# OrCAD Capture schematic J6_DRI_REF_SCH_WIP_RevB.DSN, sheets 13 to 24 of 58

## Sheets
13 SH15 - VAYU CLOCKS: size B; rev: A
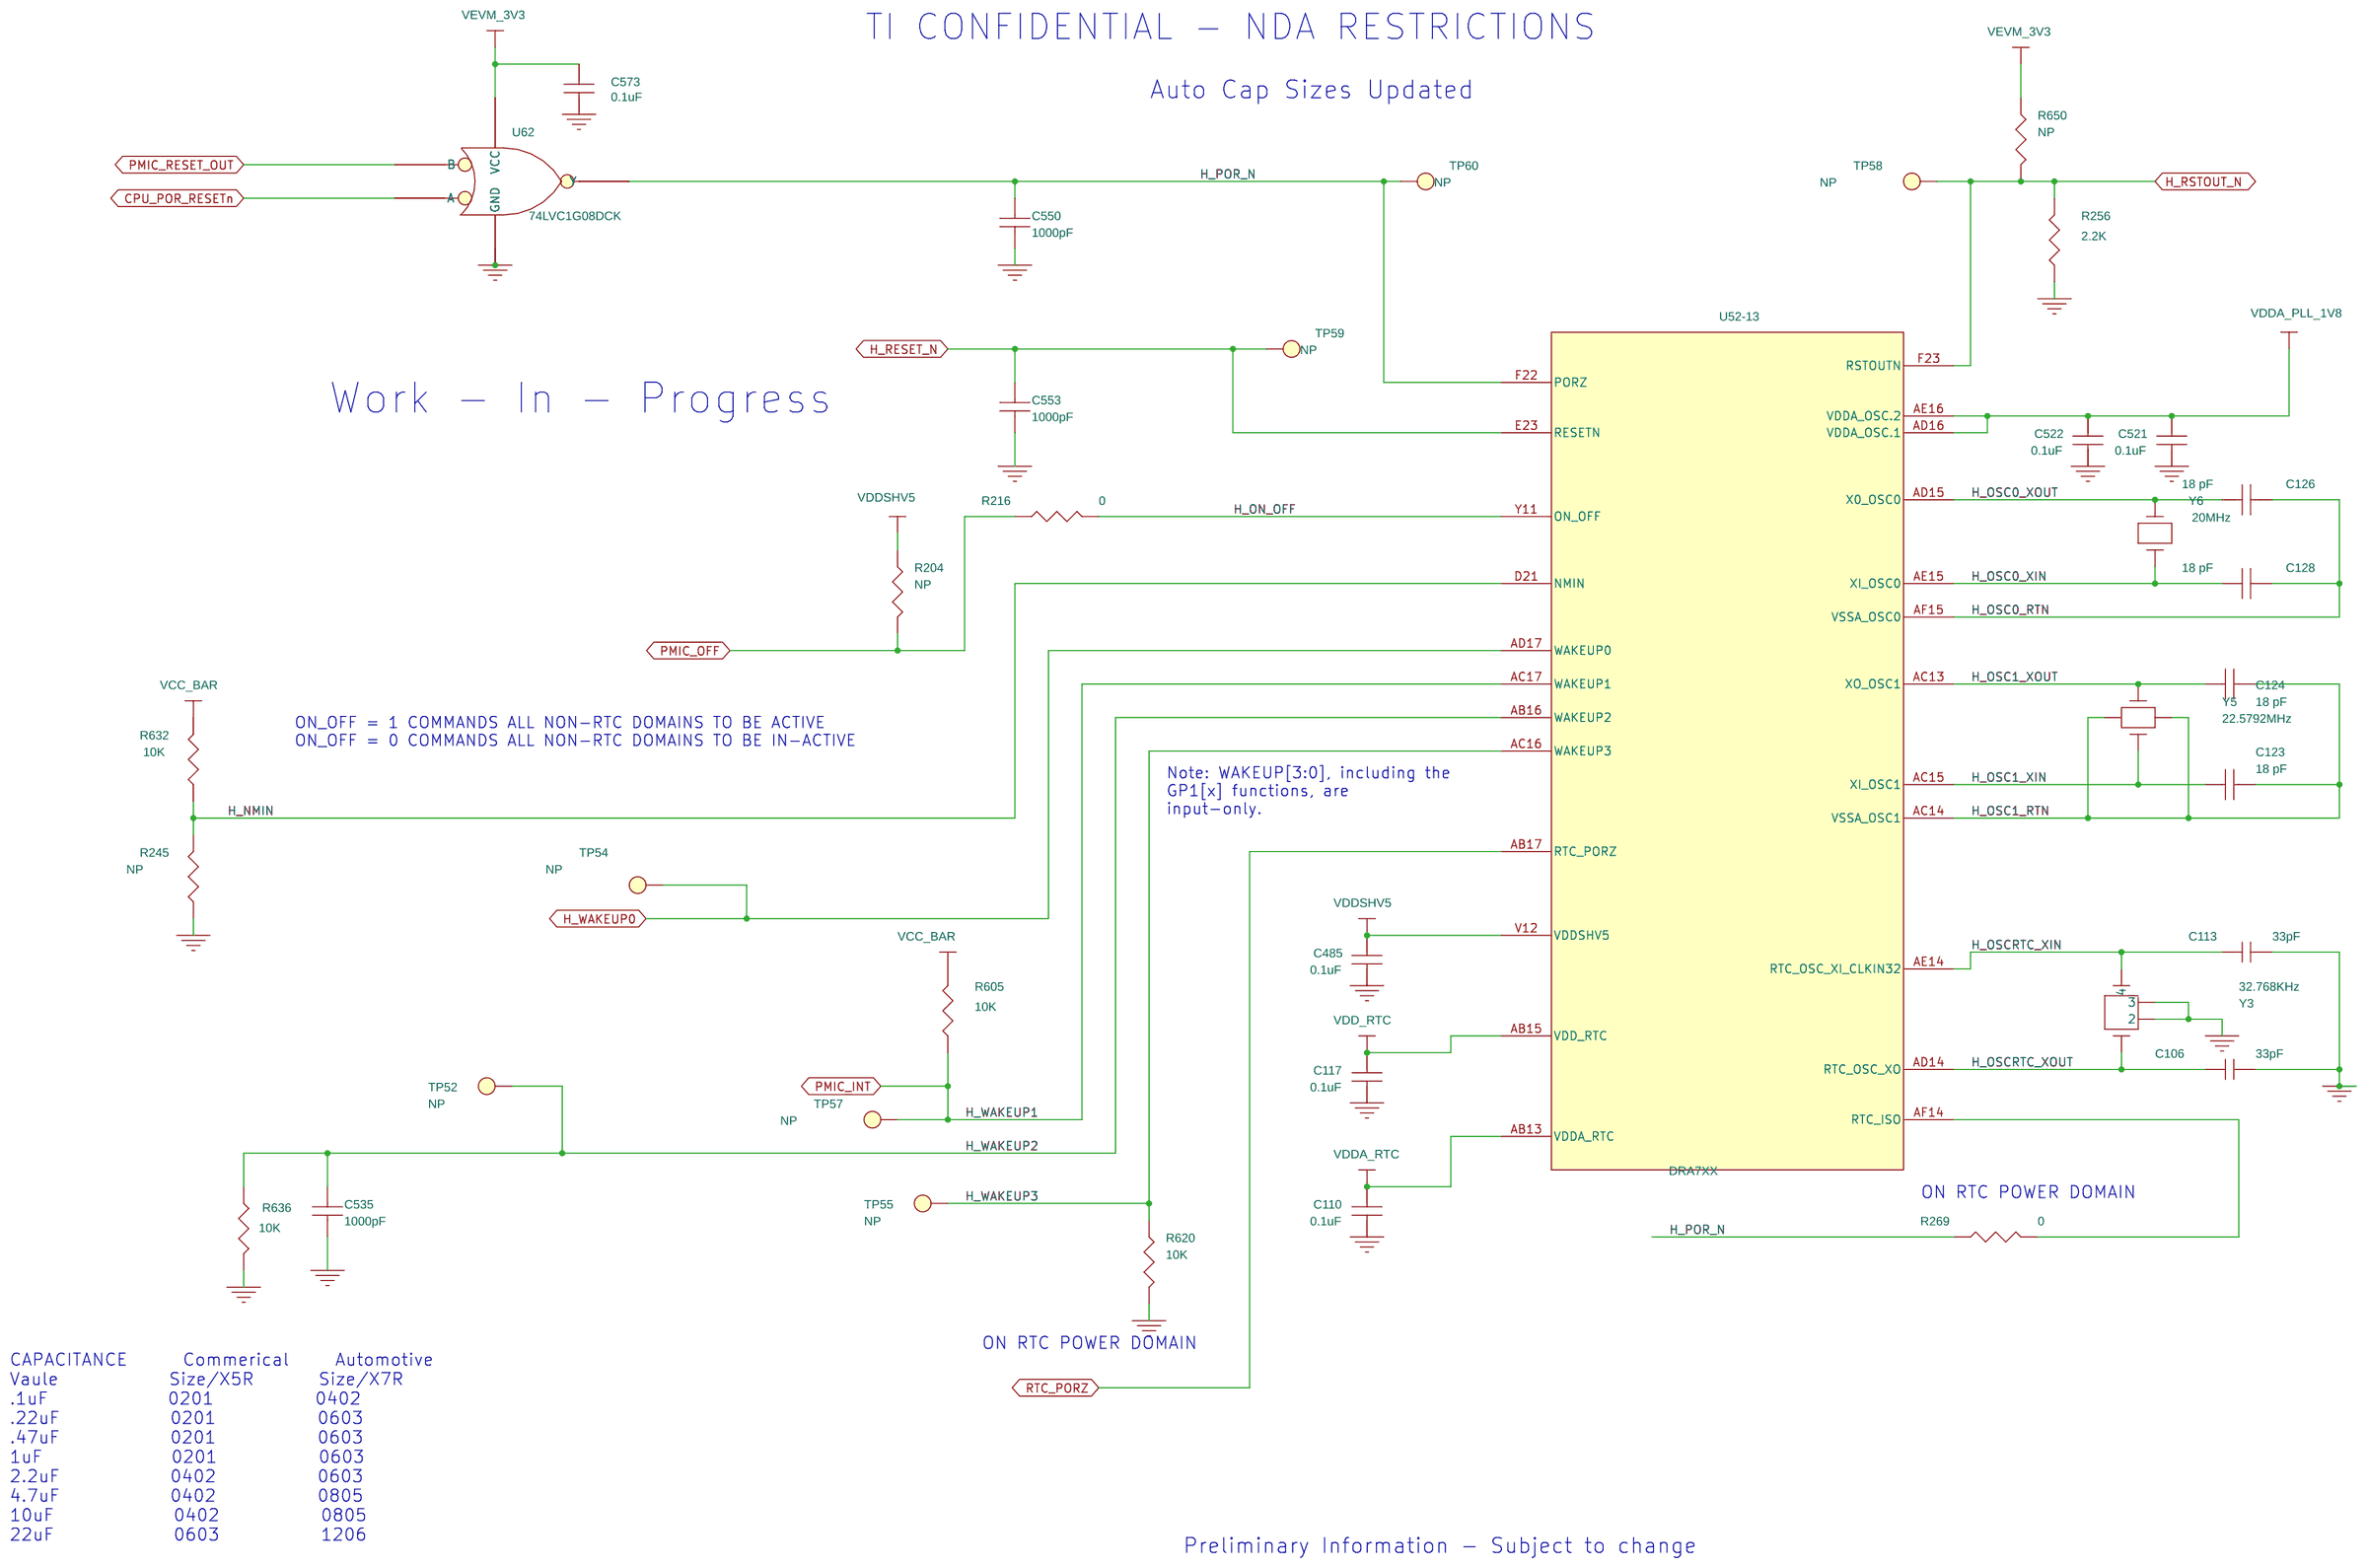
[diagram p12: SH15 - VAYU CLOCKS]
14 SH16 - VAYU INTERNAL LDOS: size B; rev: A
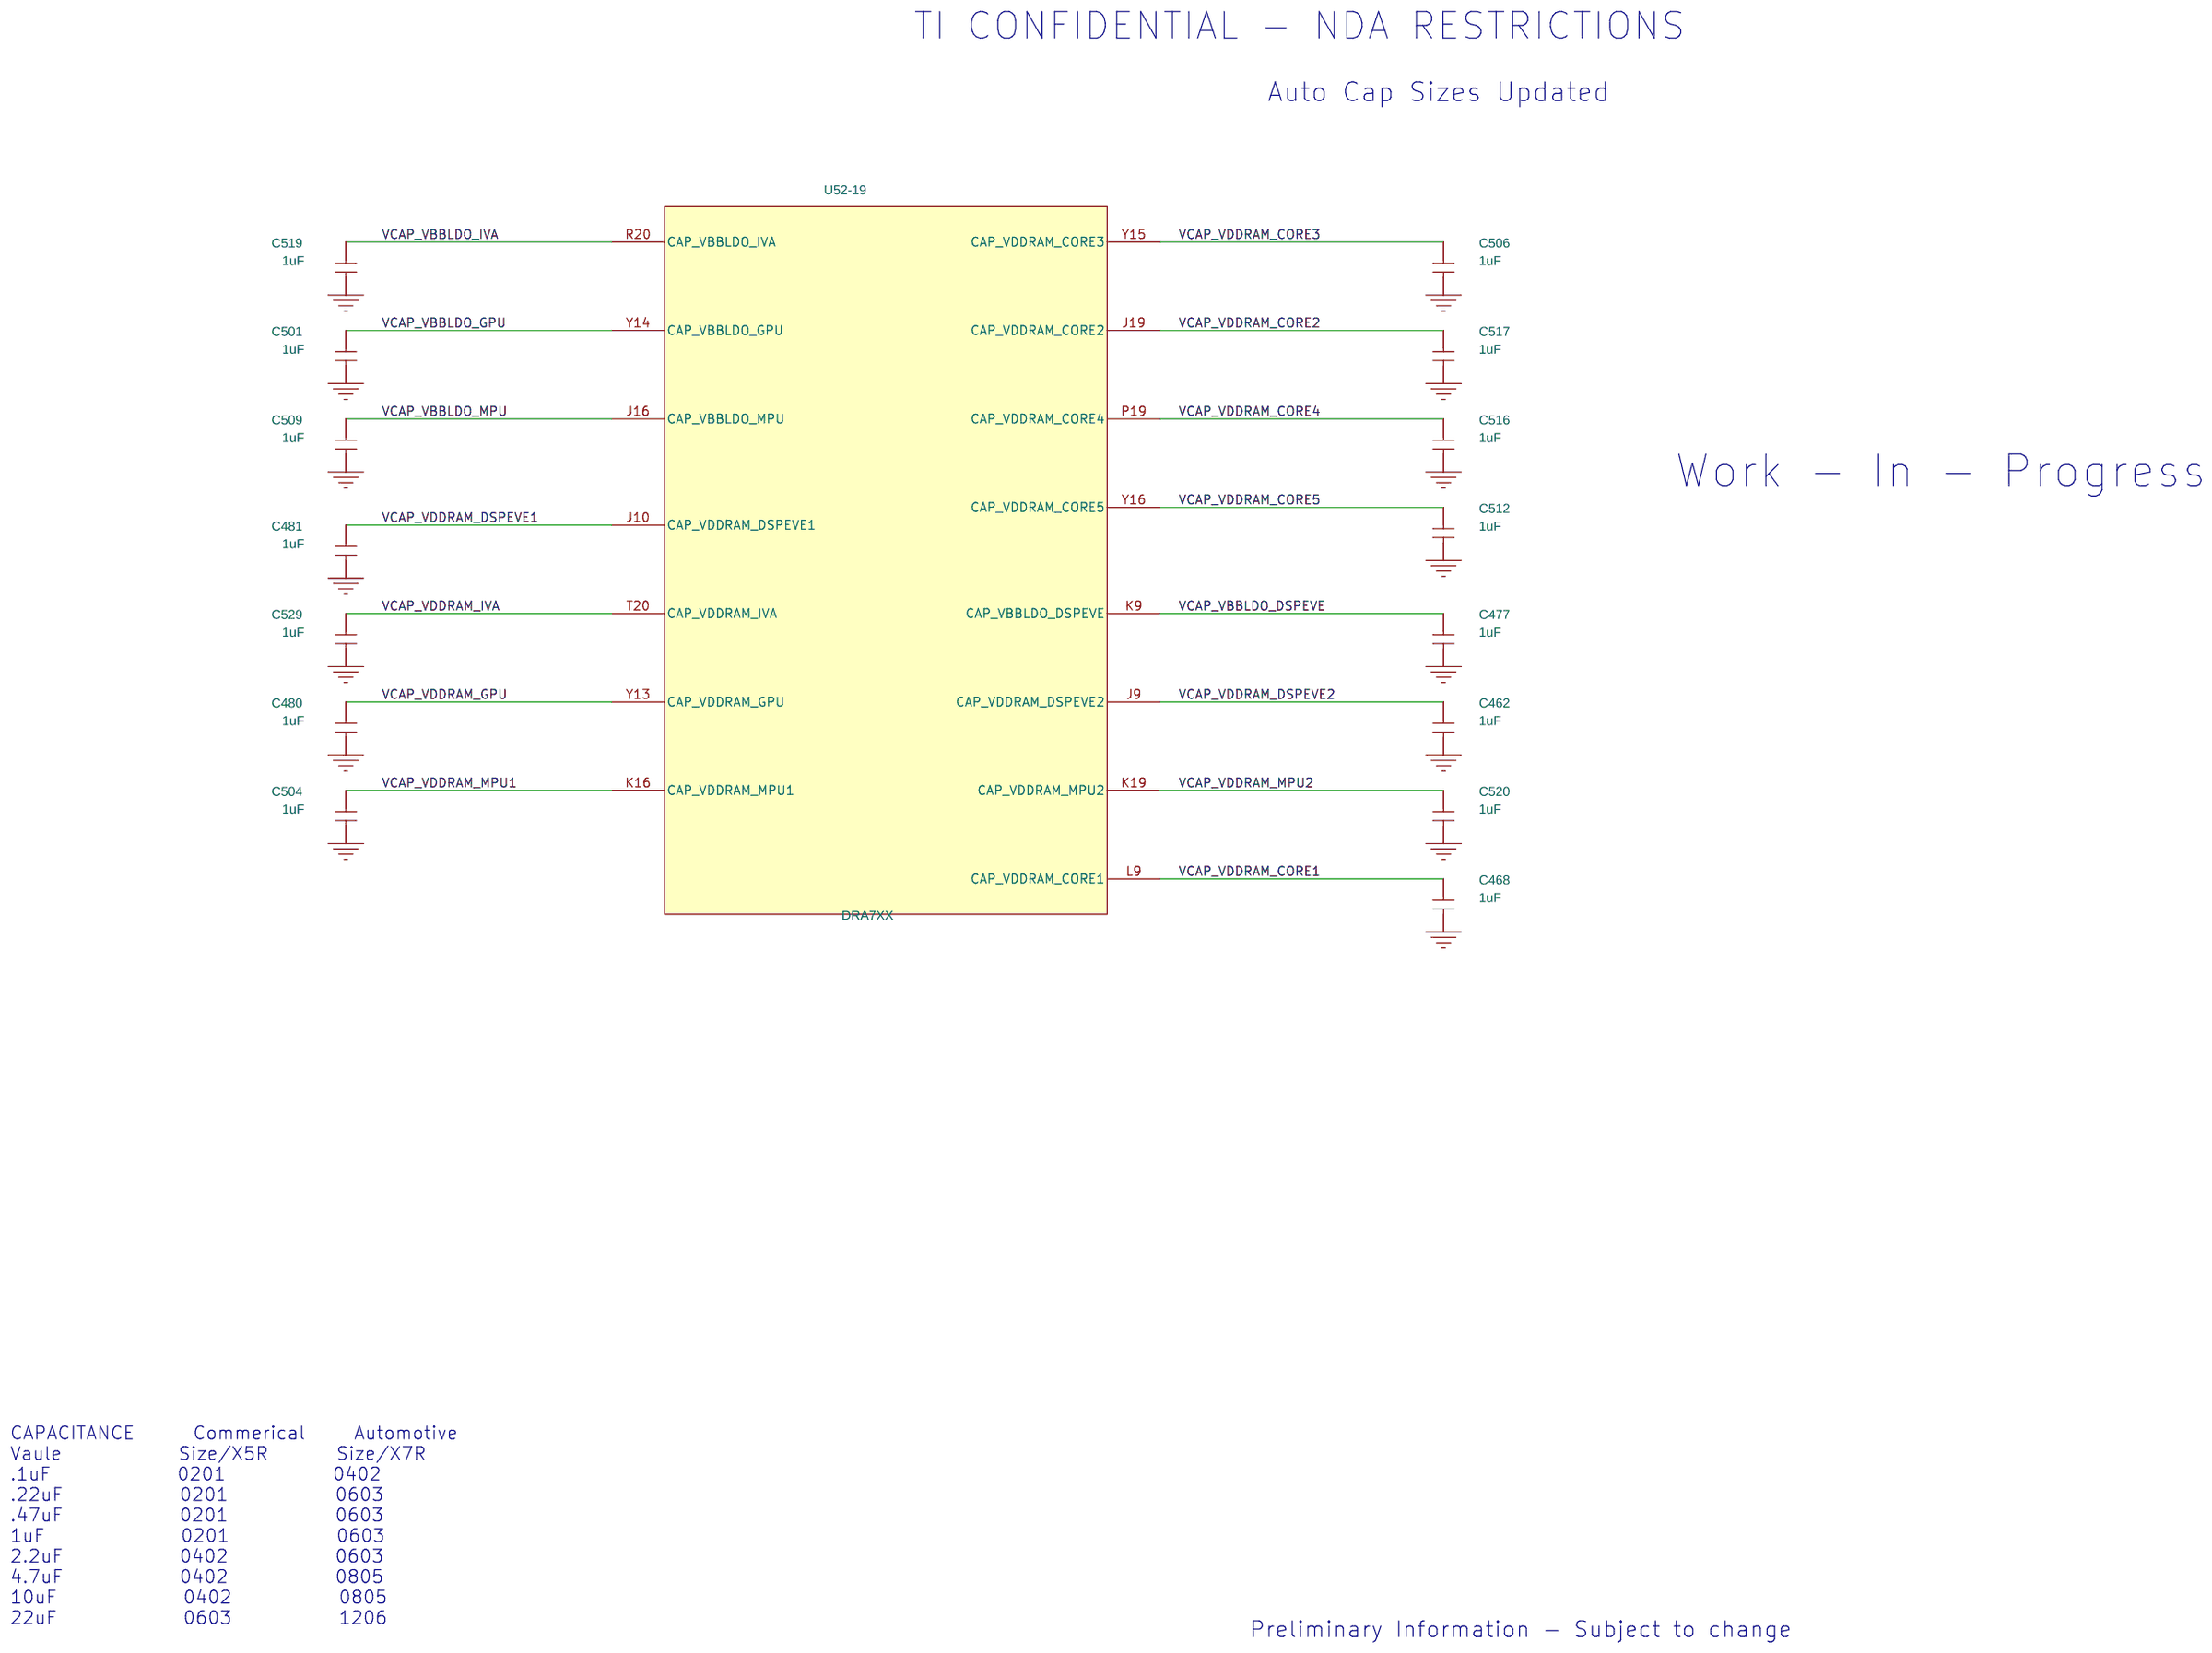
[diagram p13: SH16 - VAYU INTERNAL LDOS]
15 SH17 - VAYU IO POWER: size B; rev: A
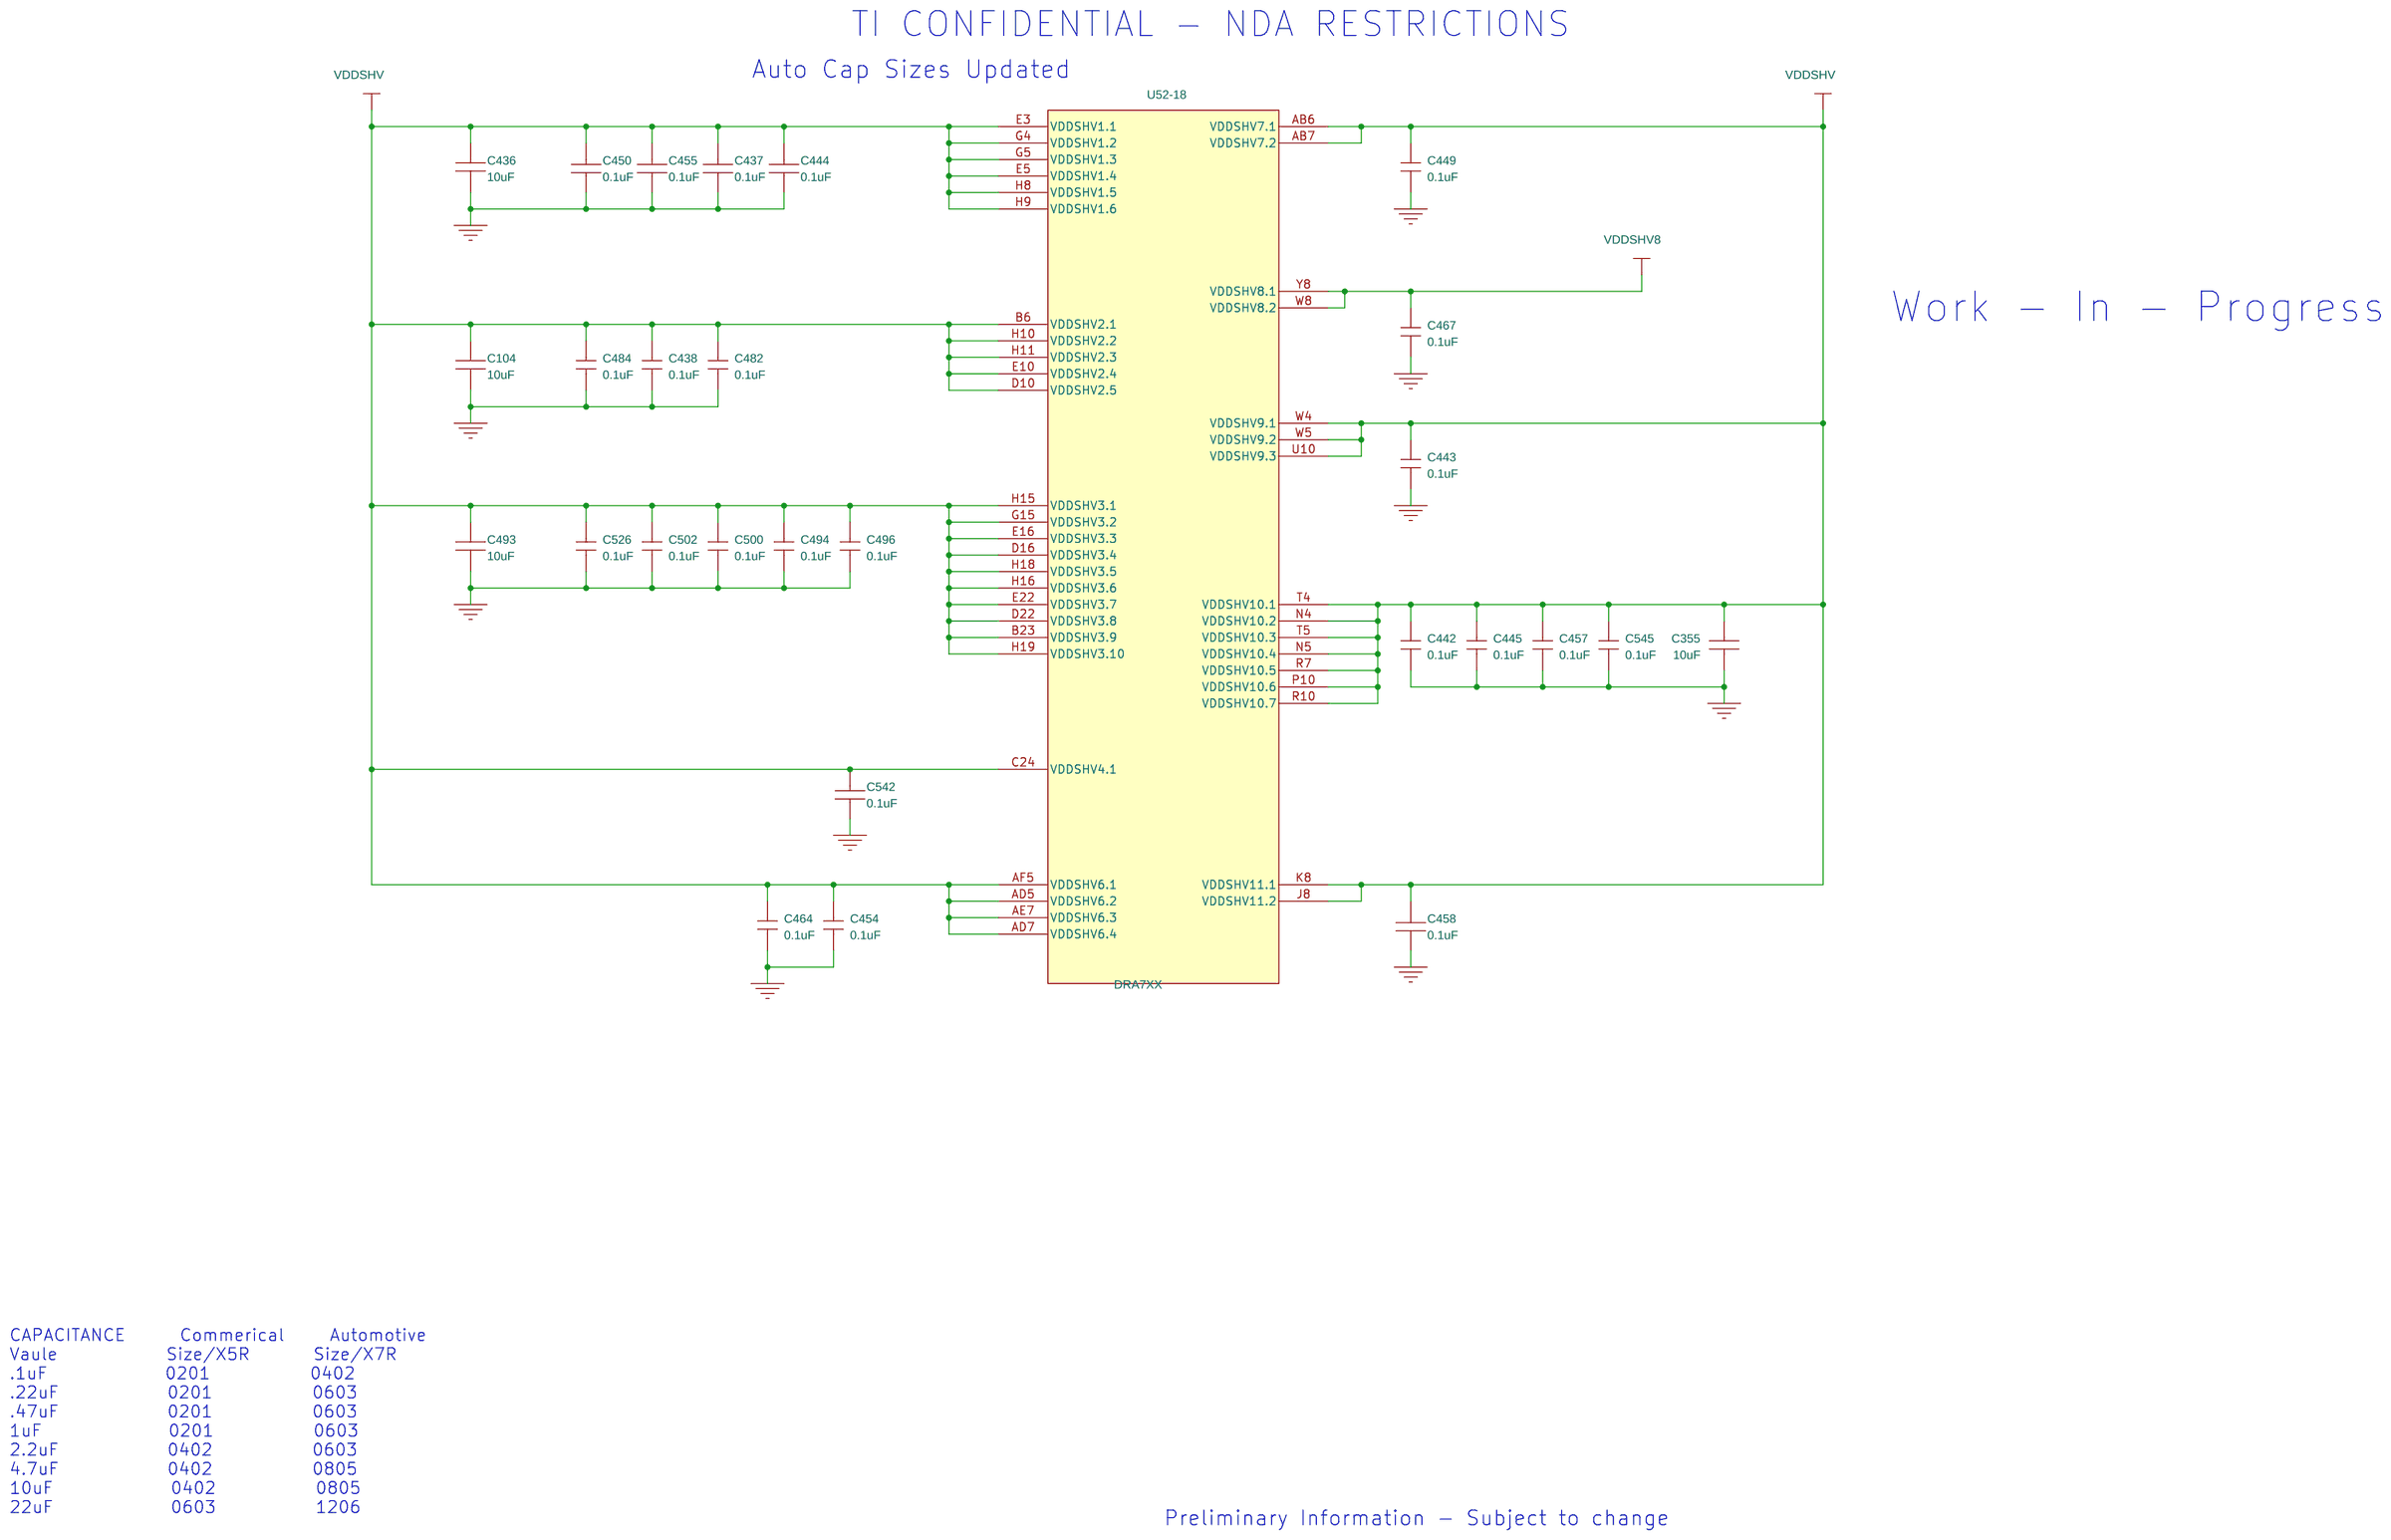
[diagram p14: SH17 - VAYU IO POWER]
16 SH18 - VAYU 1V8 DIGITAL POWER: size B; rev: A
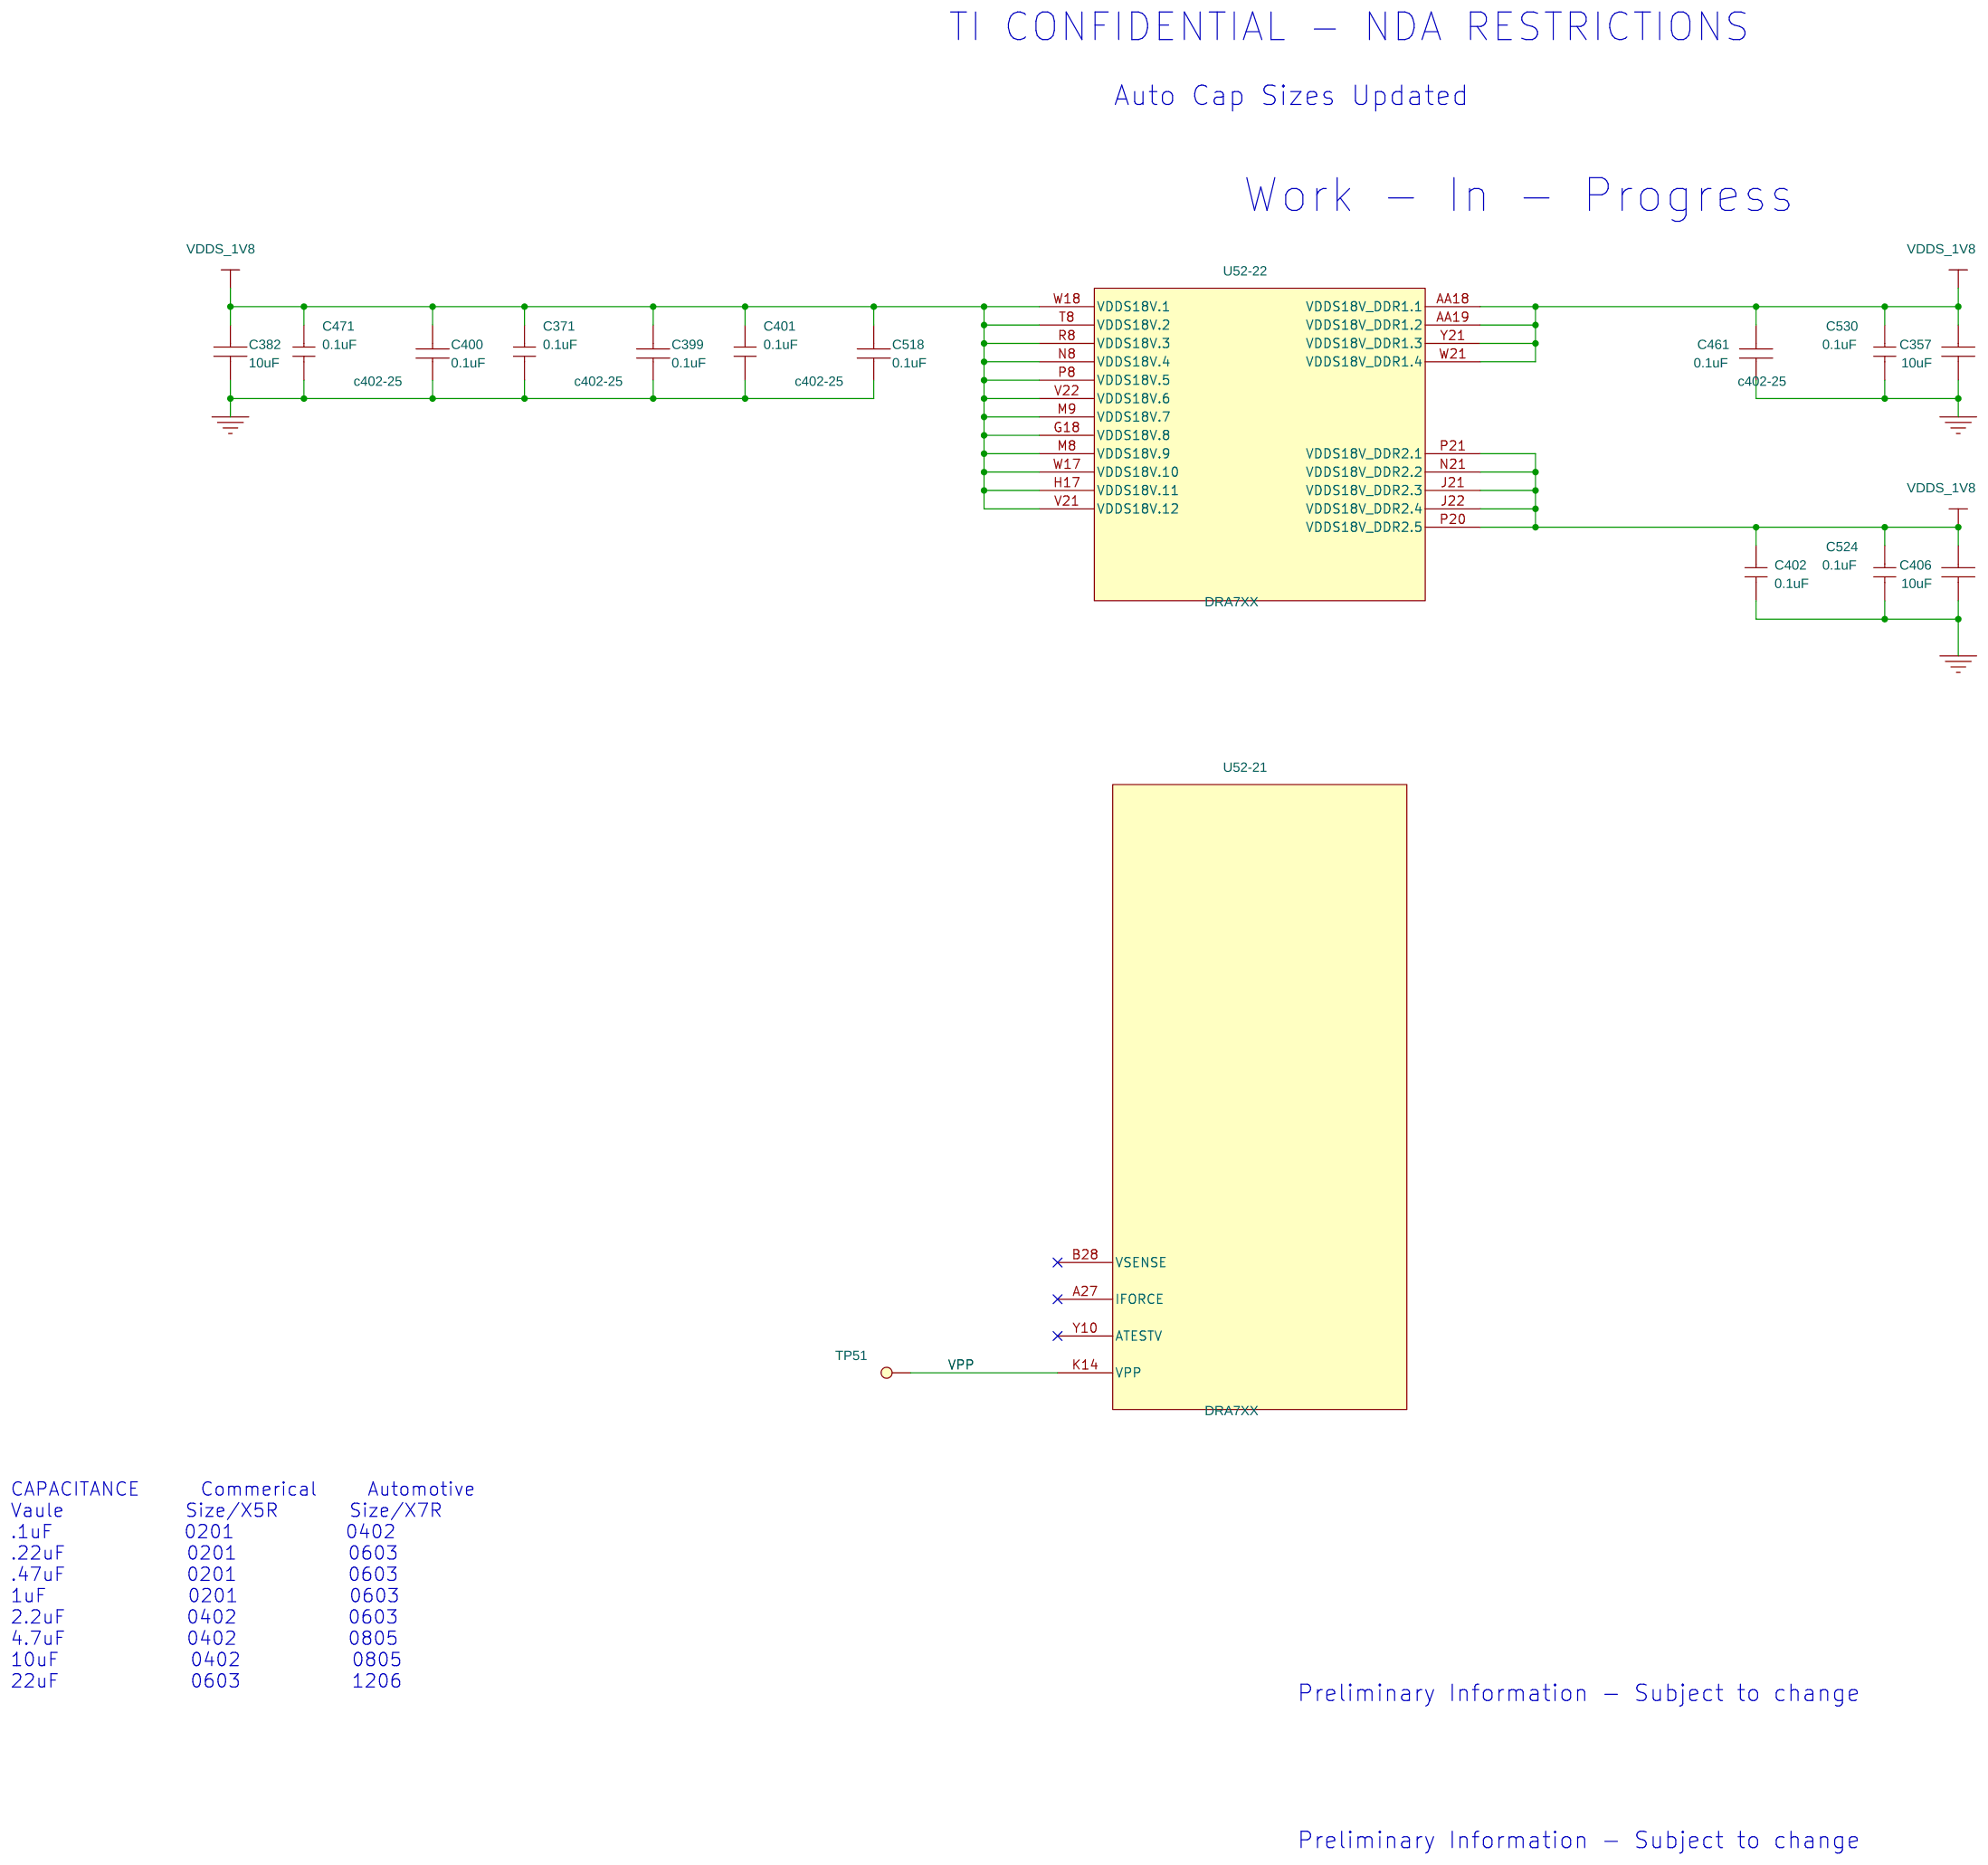
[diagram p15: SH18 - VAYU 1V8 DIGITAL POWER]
17 SH19 - VAYU DDR POWER: size B
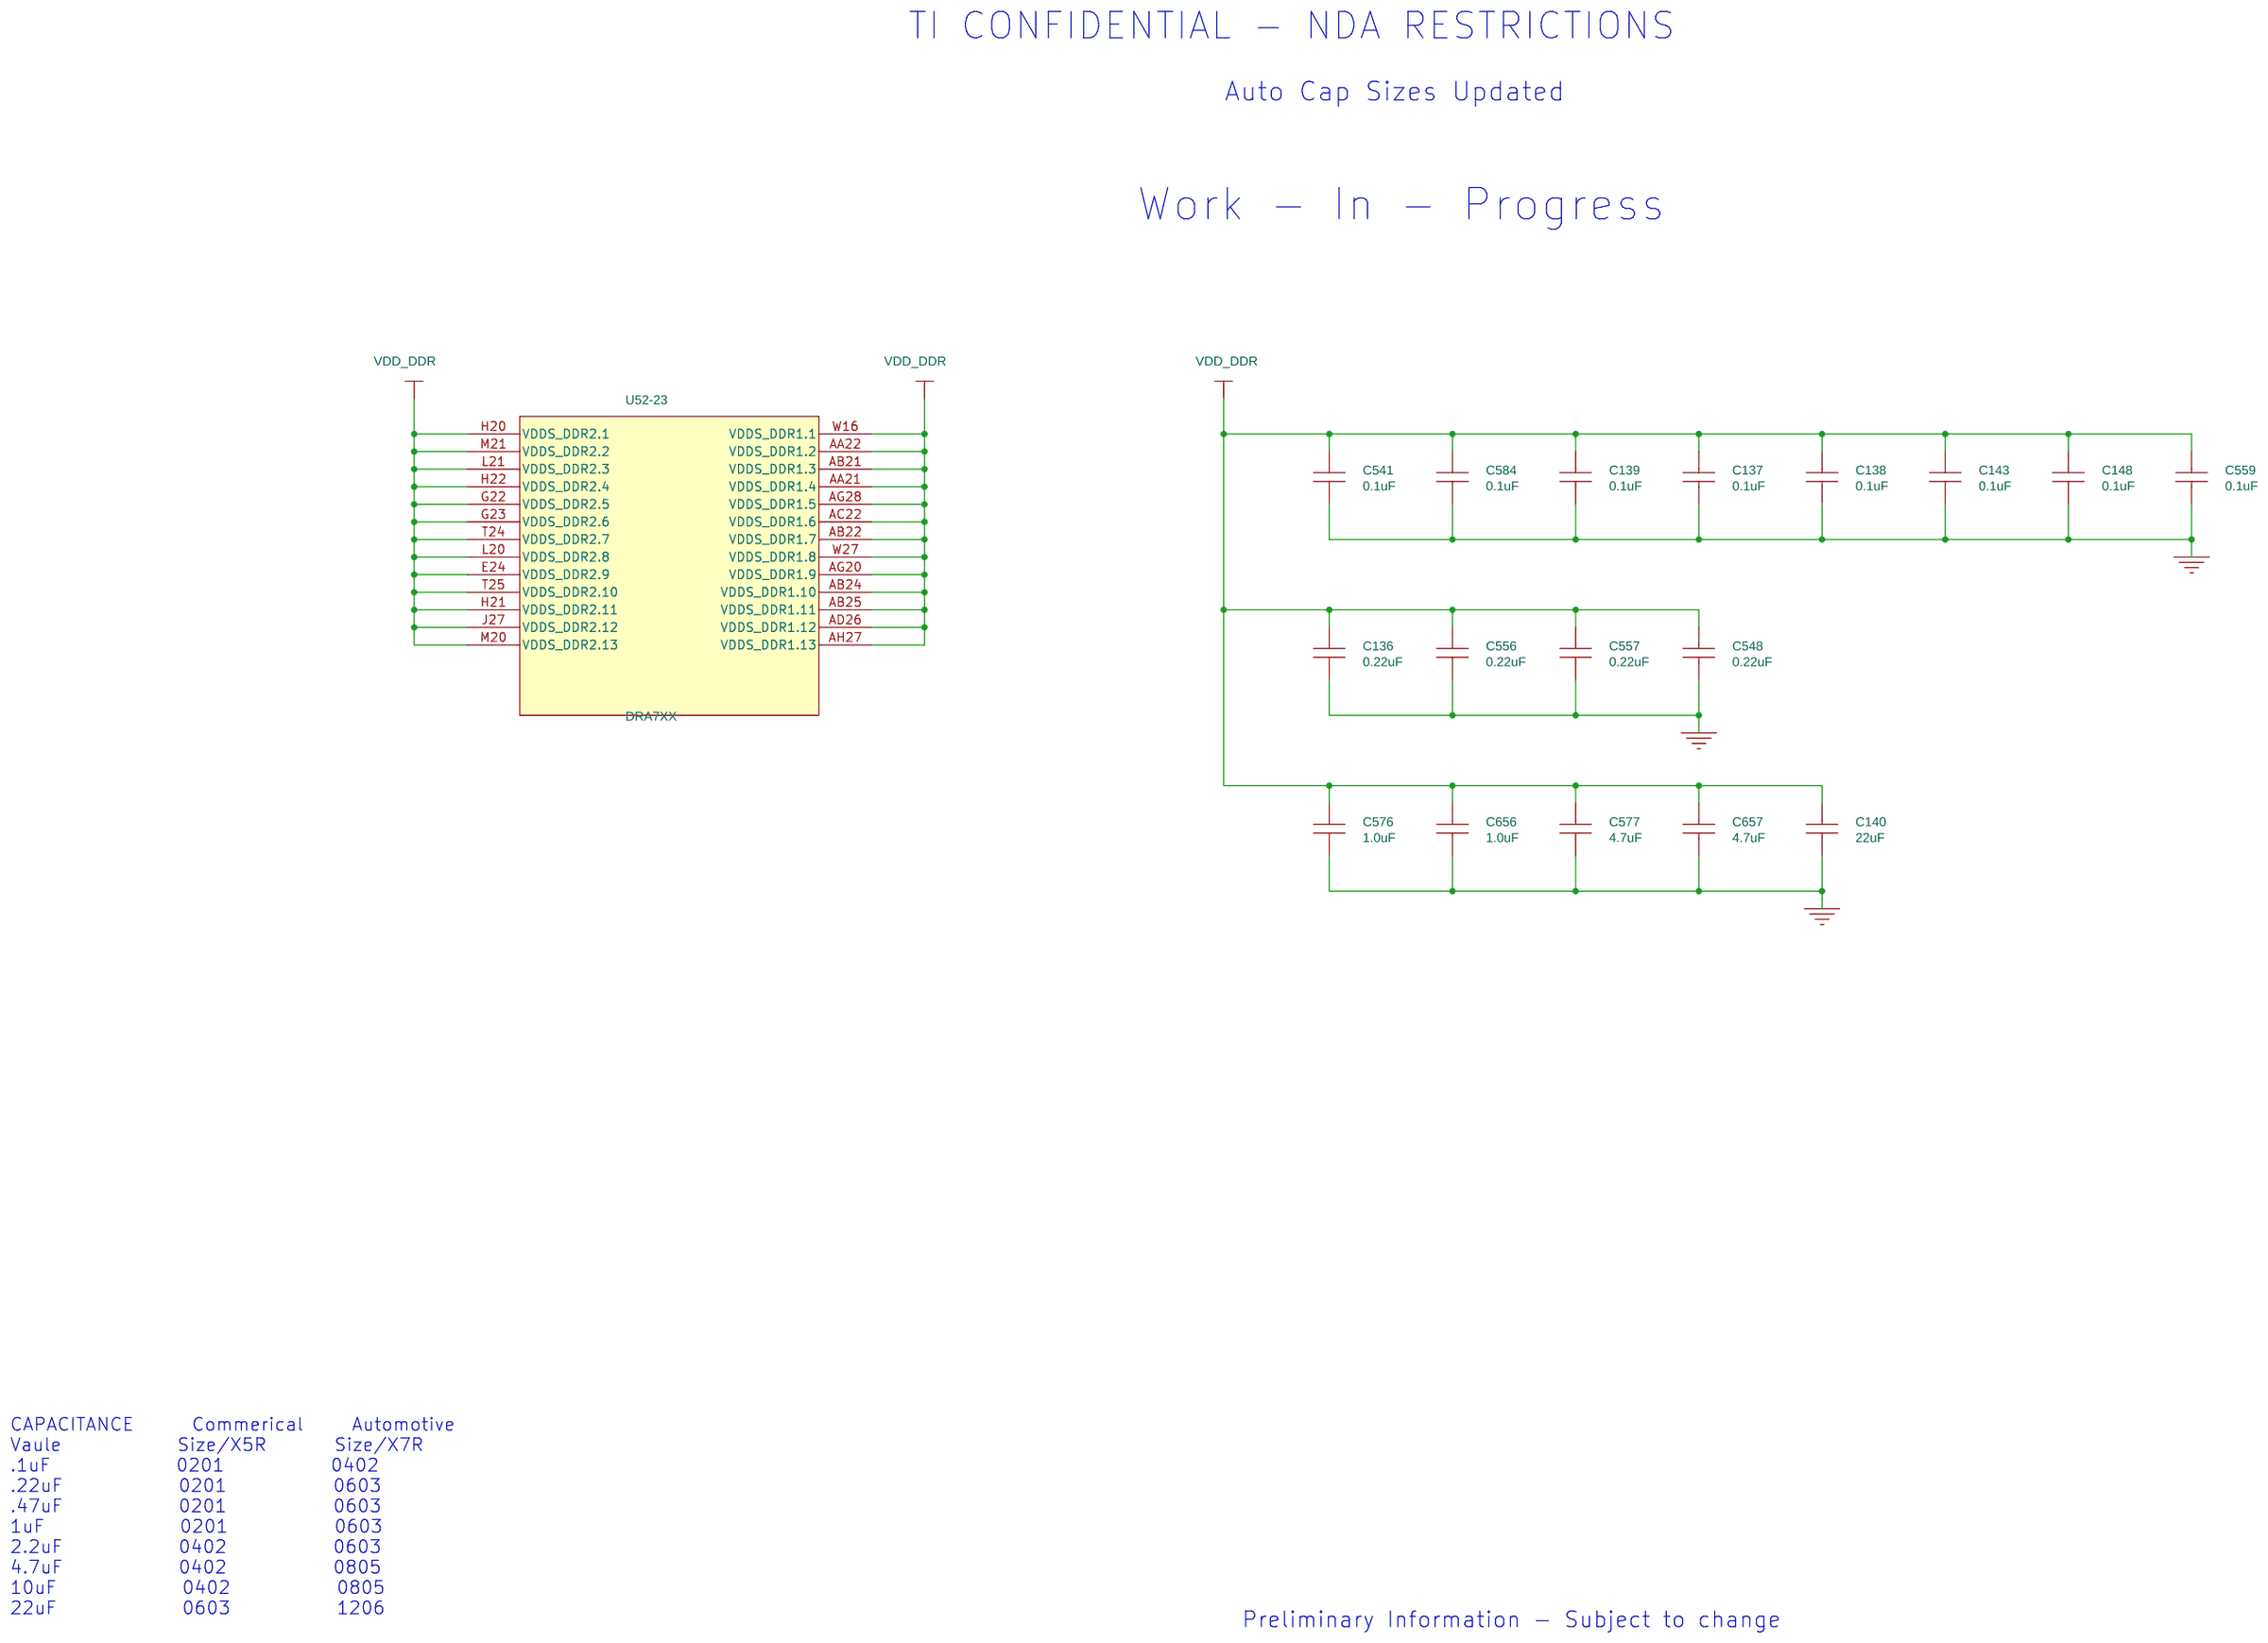
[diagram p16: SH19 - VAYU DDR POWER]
18 SH20 - VAYU 1V8 ANALOG POWER: size B; rev: A
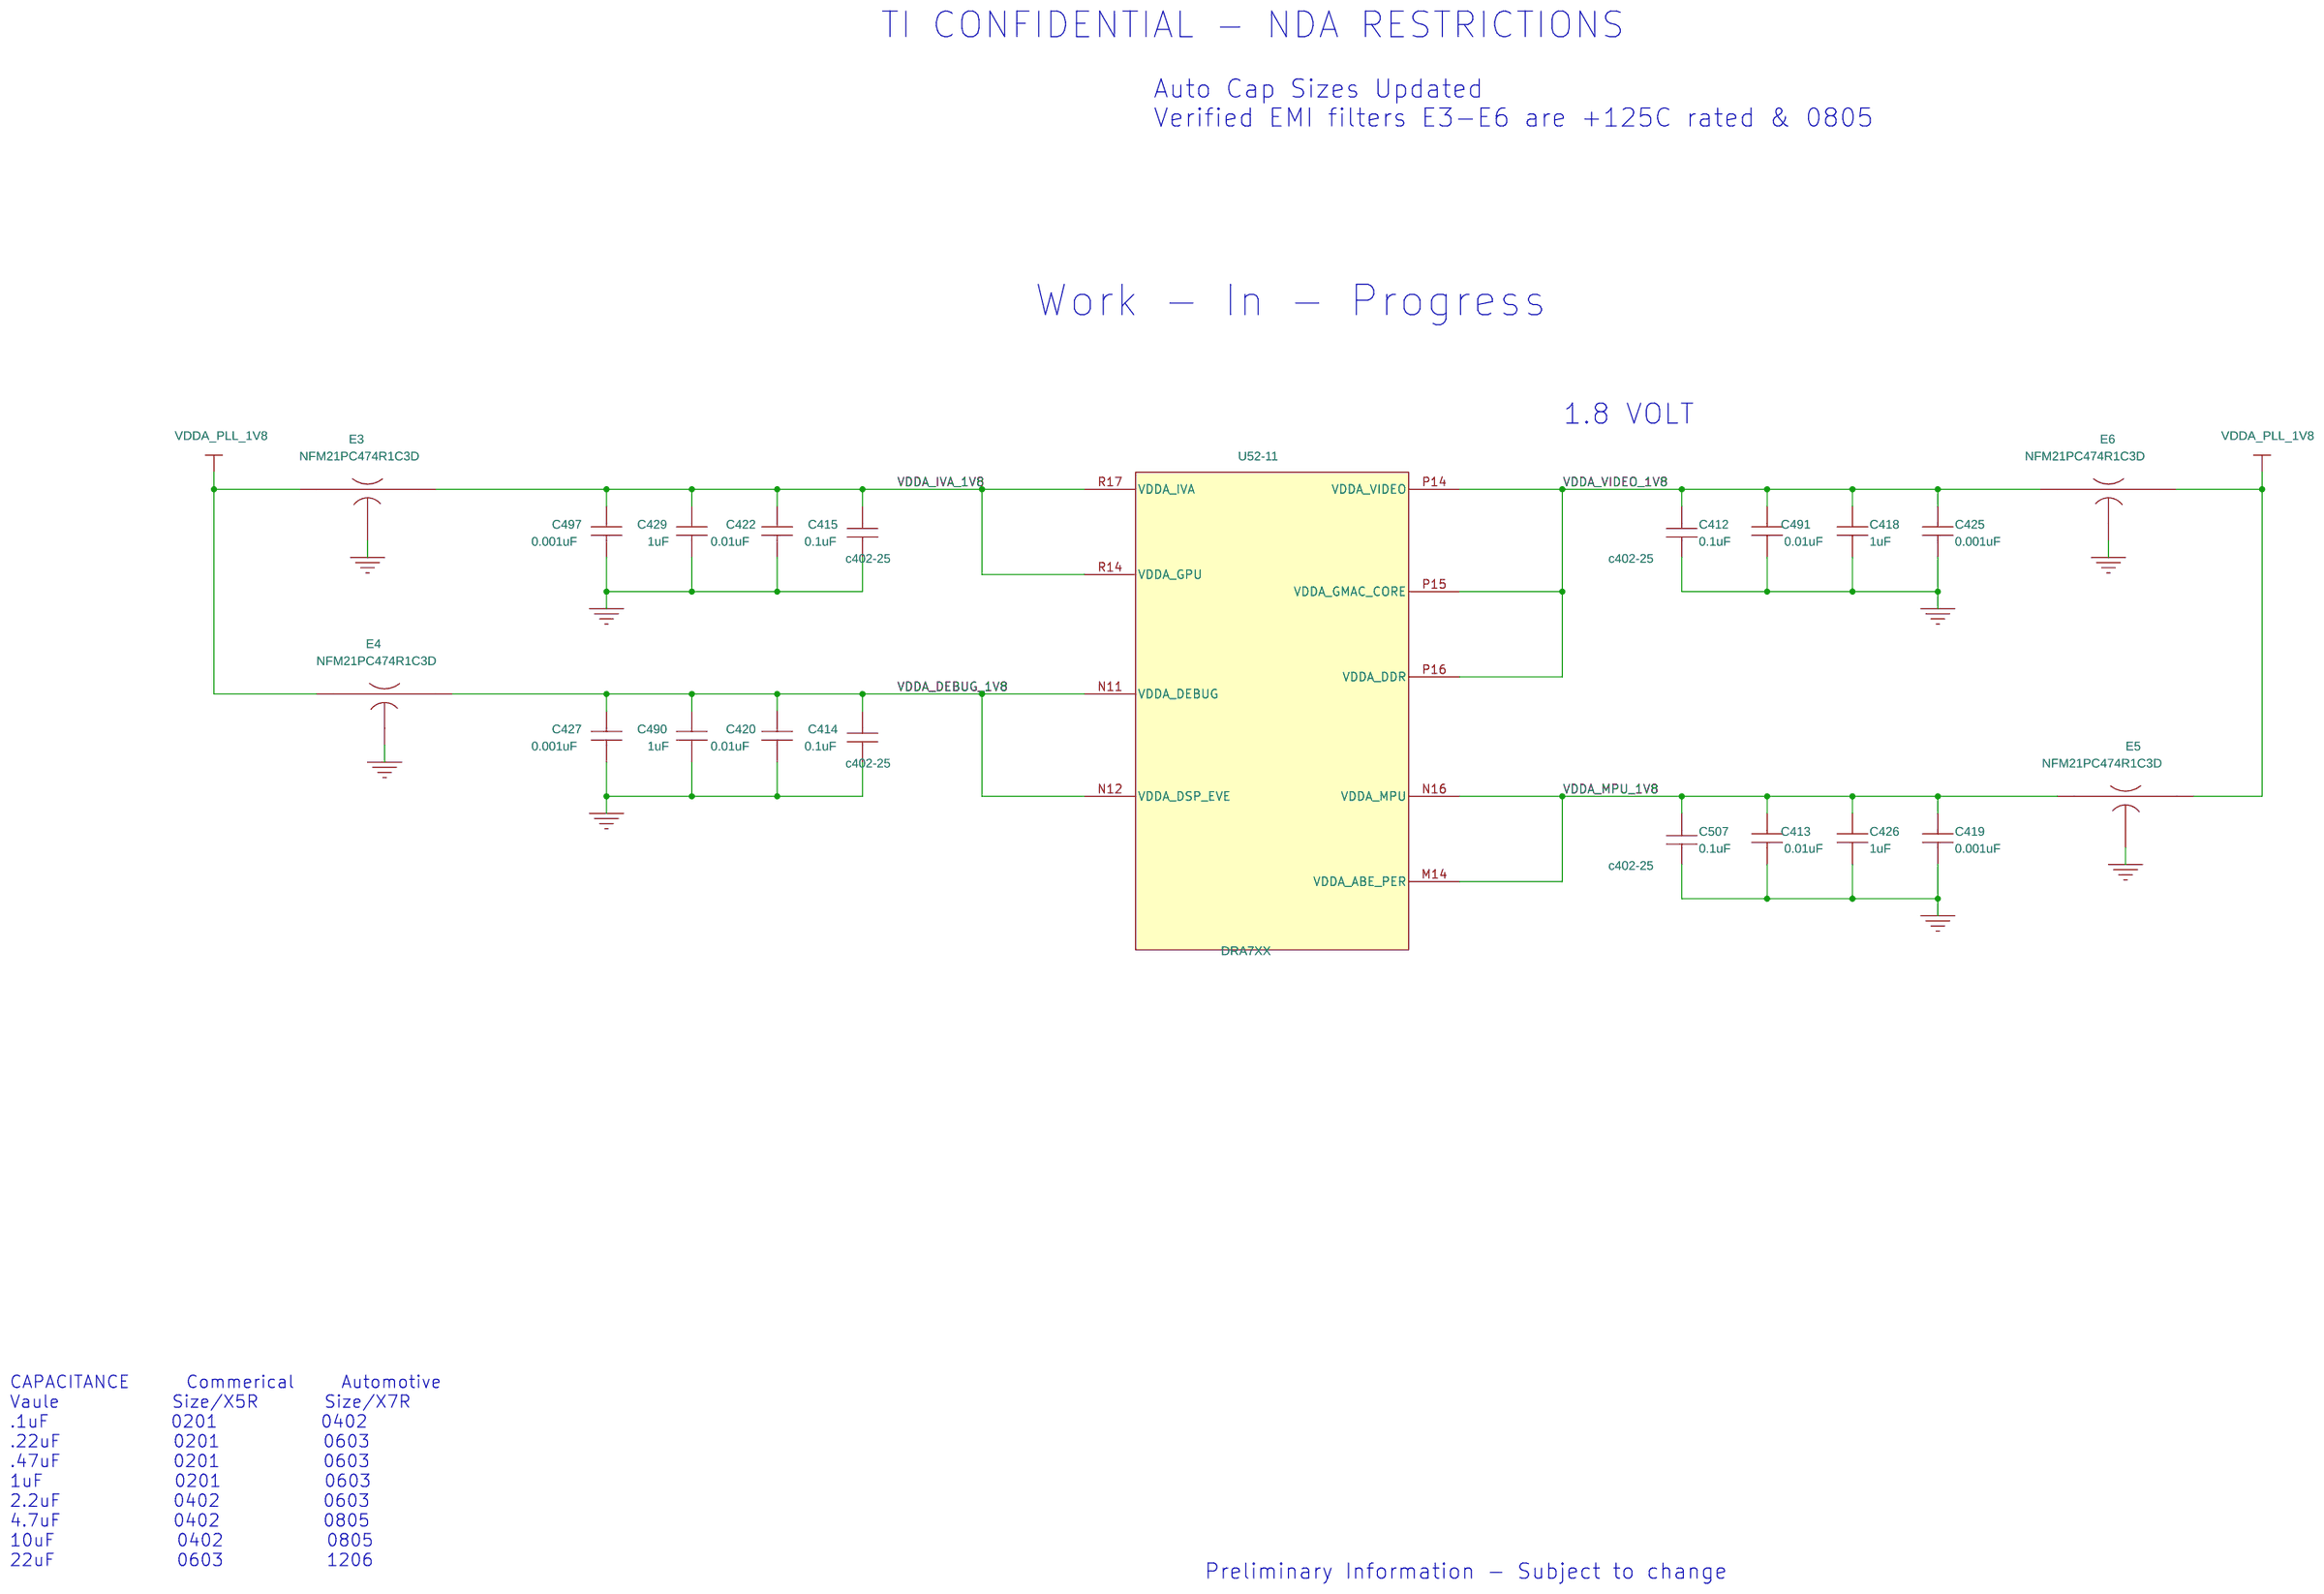
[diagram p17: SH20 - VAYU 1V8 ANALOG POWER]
19 SH21 - VAYU AVS POWER: size B
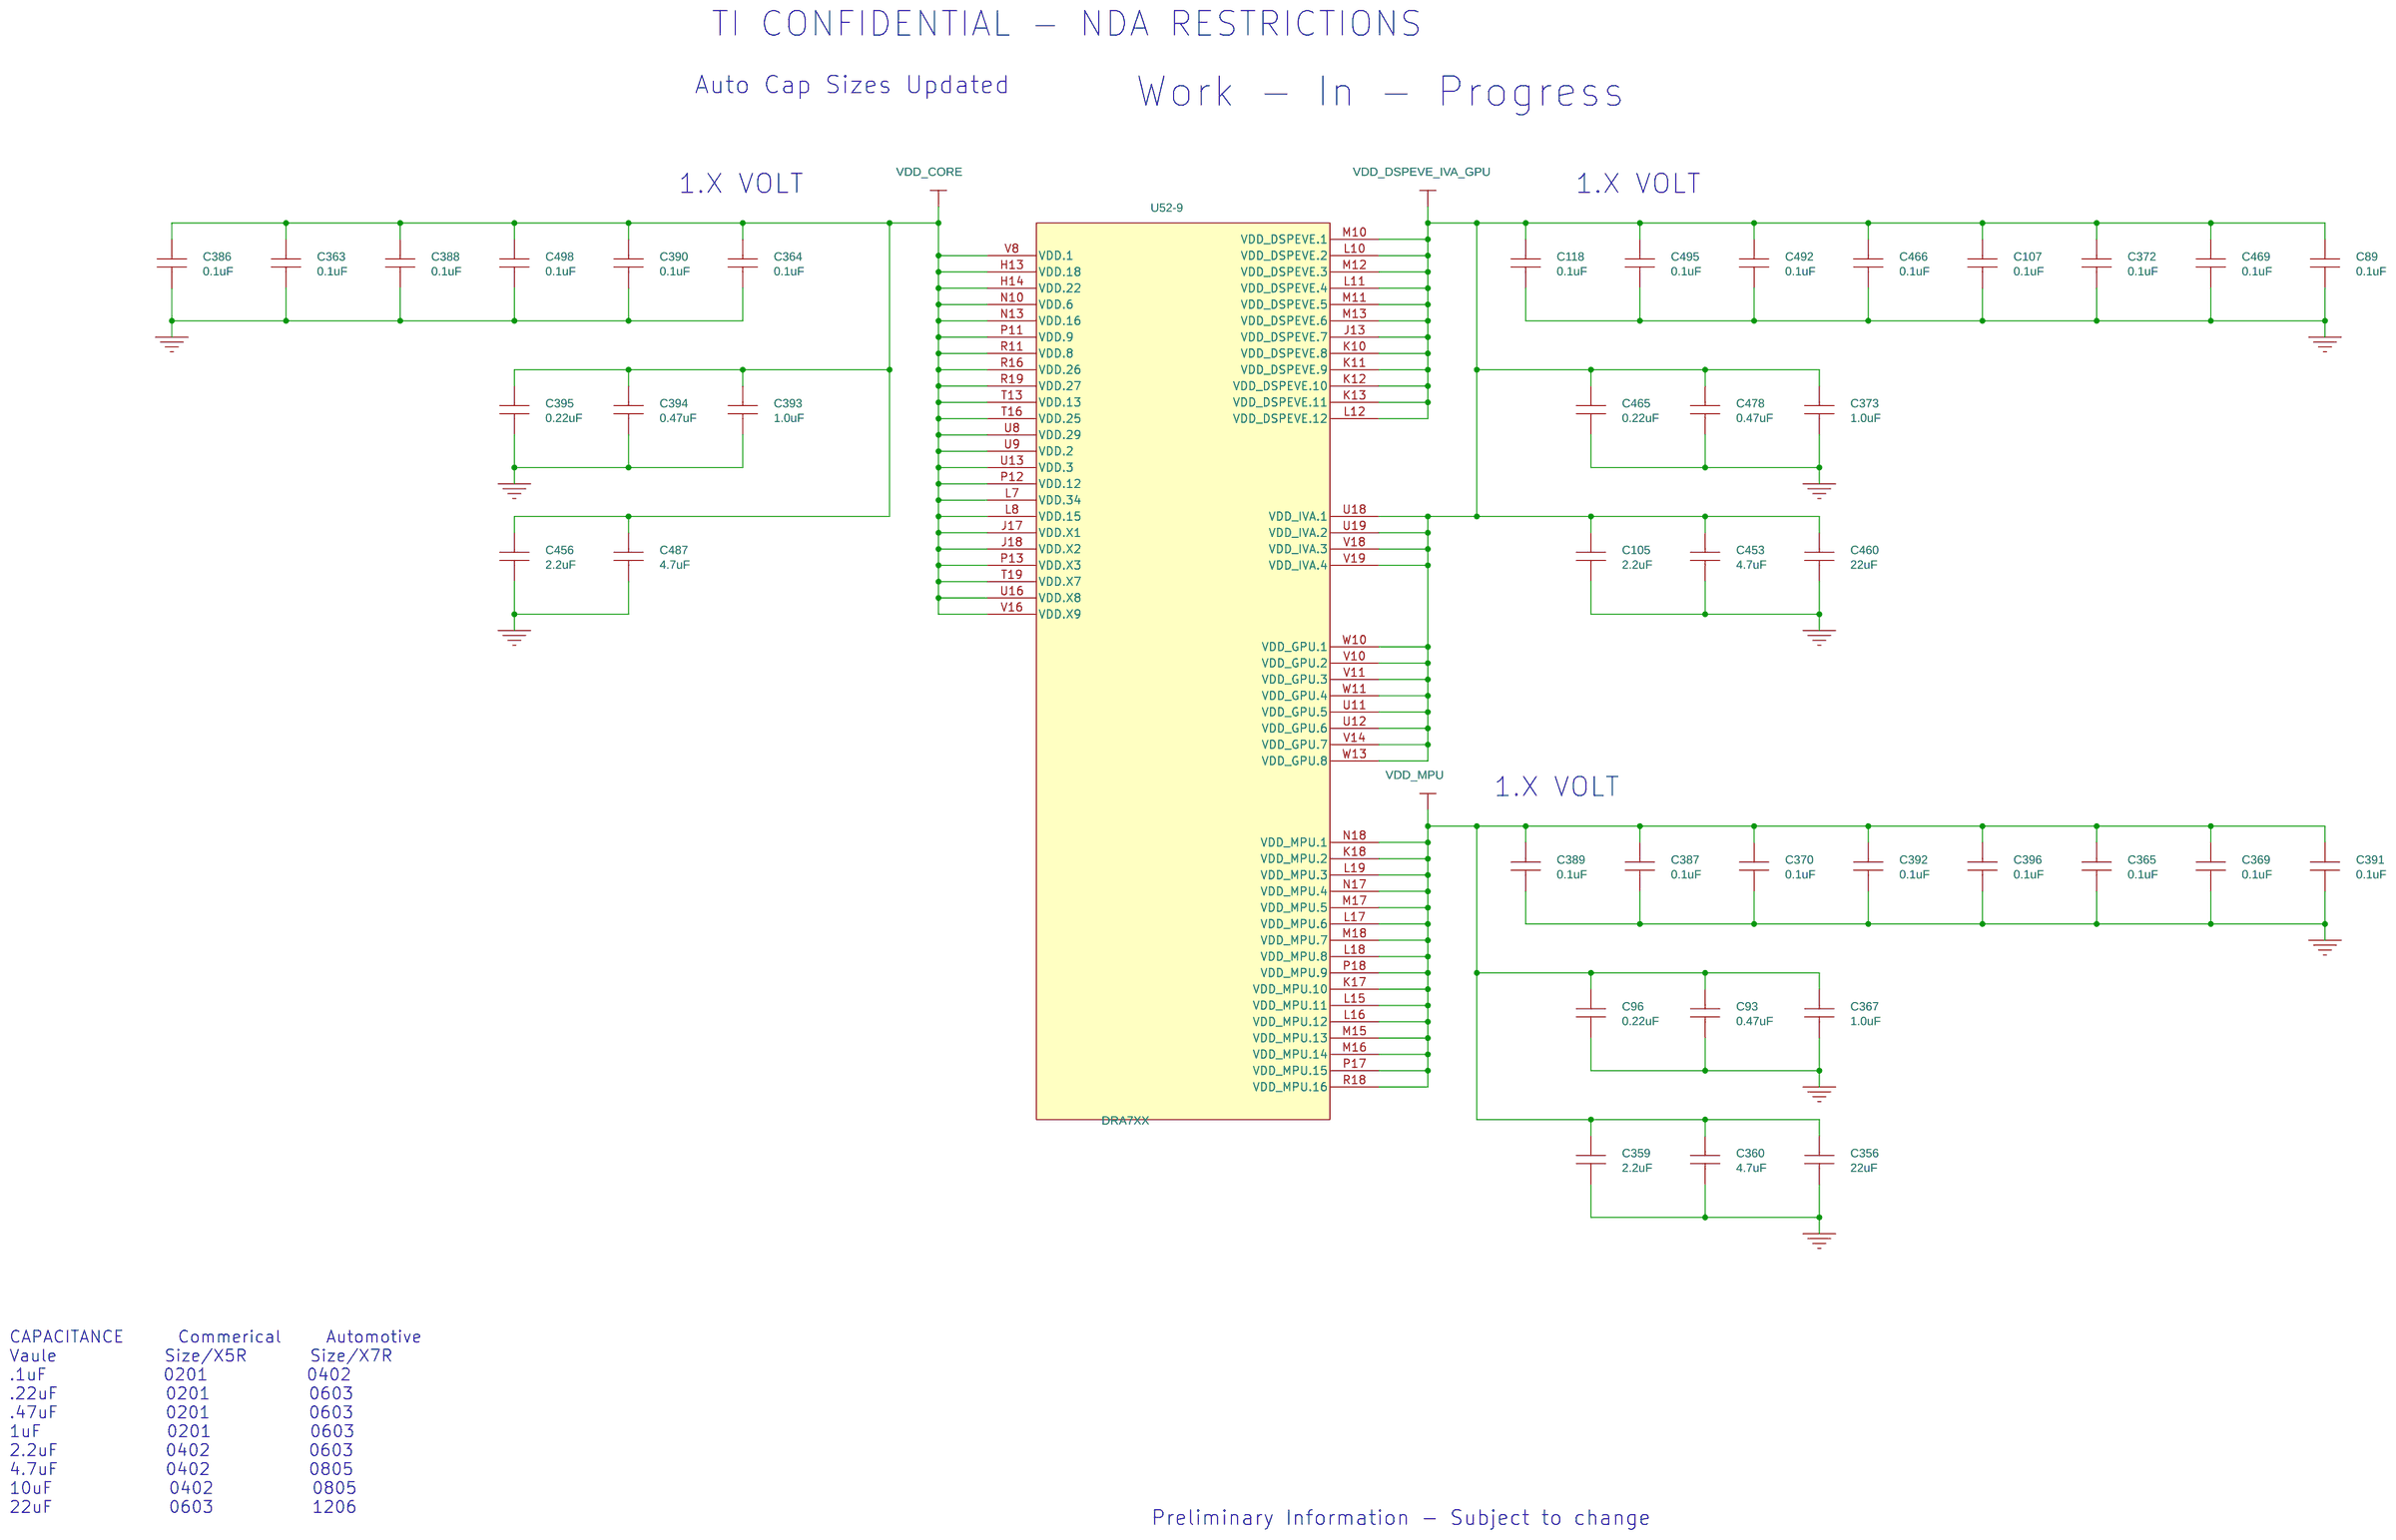
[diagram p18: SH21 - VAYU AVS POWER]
20 SH22 - VAYU GROUND: size B; rev: A
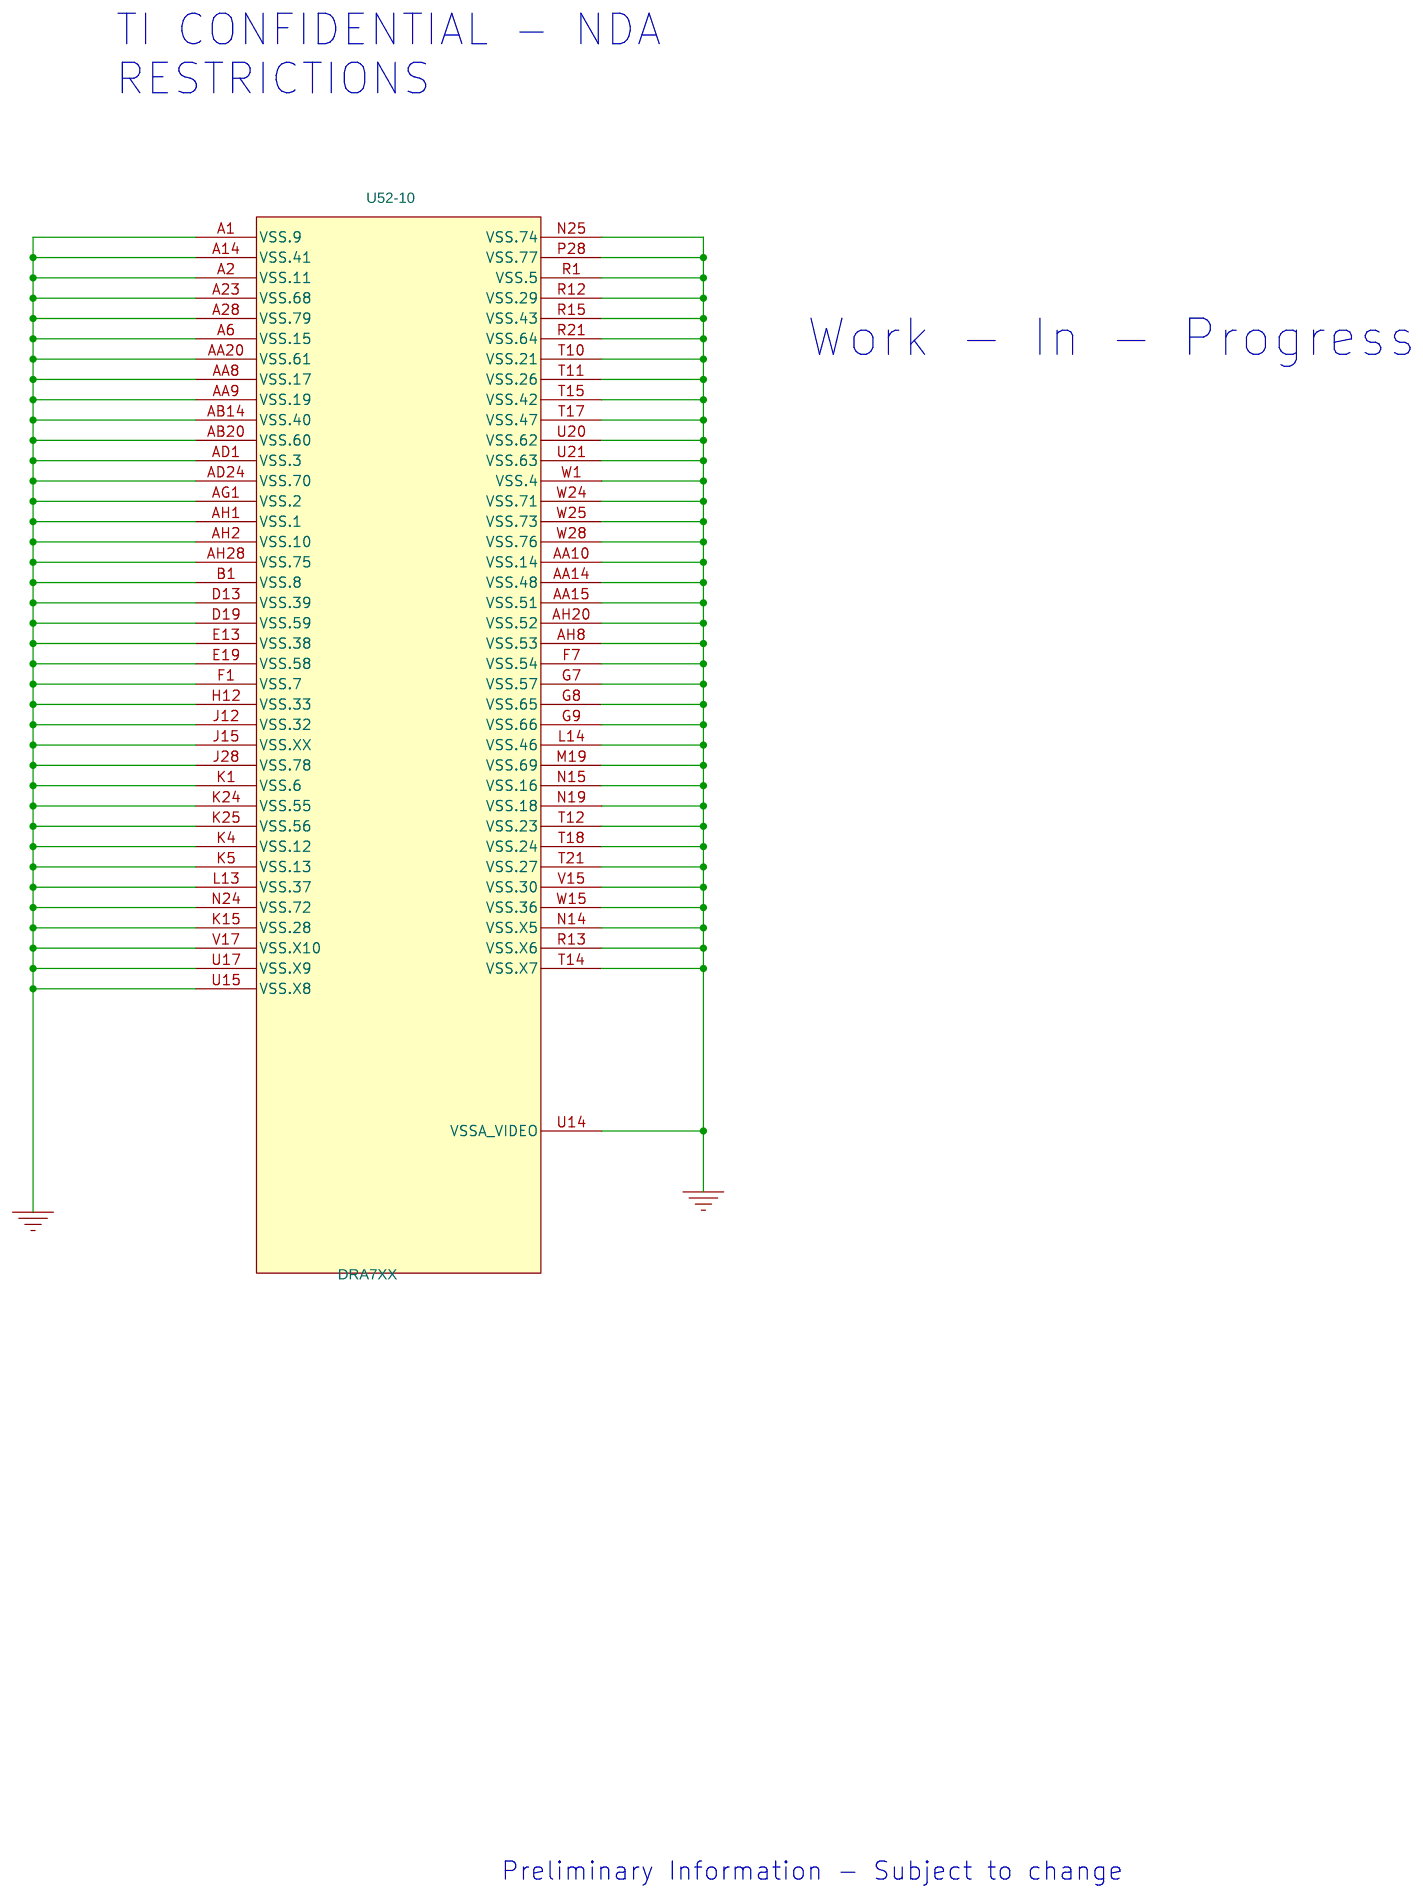
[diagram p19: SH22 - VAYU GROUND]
21 SH23 - eMMC MEMORY: size B; rev: A
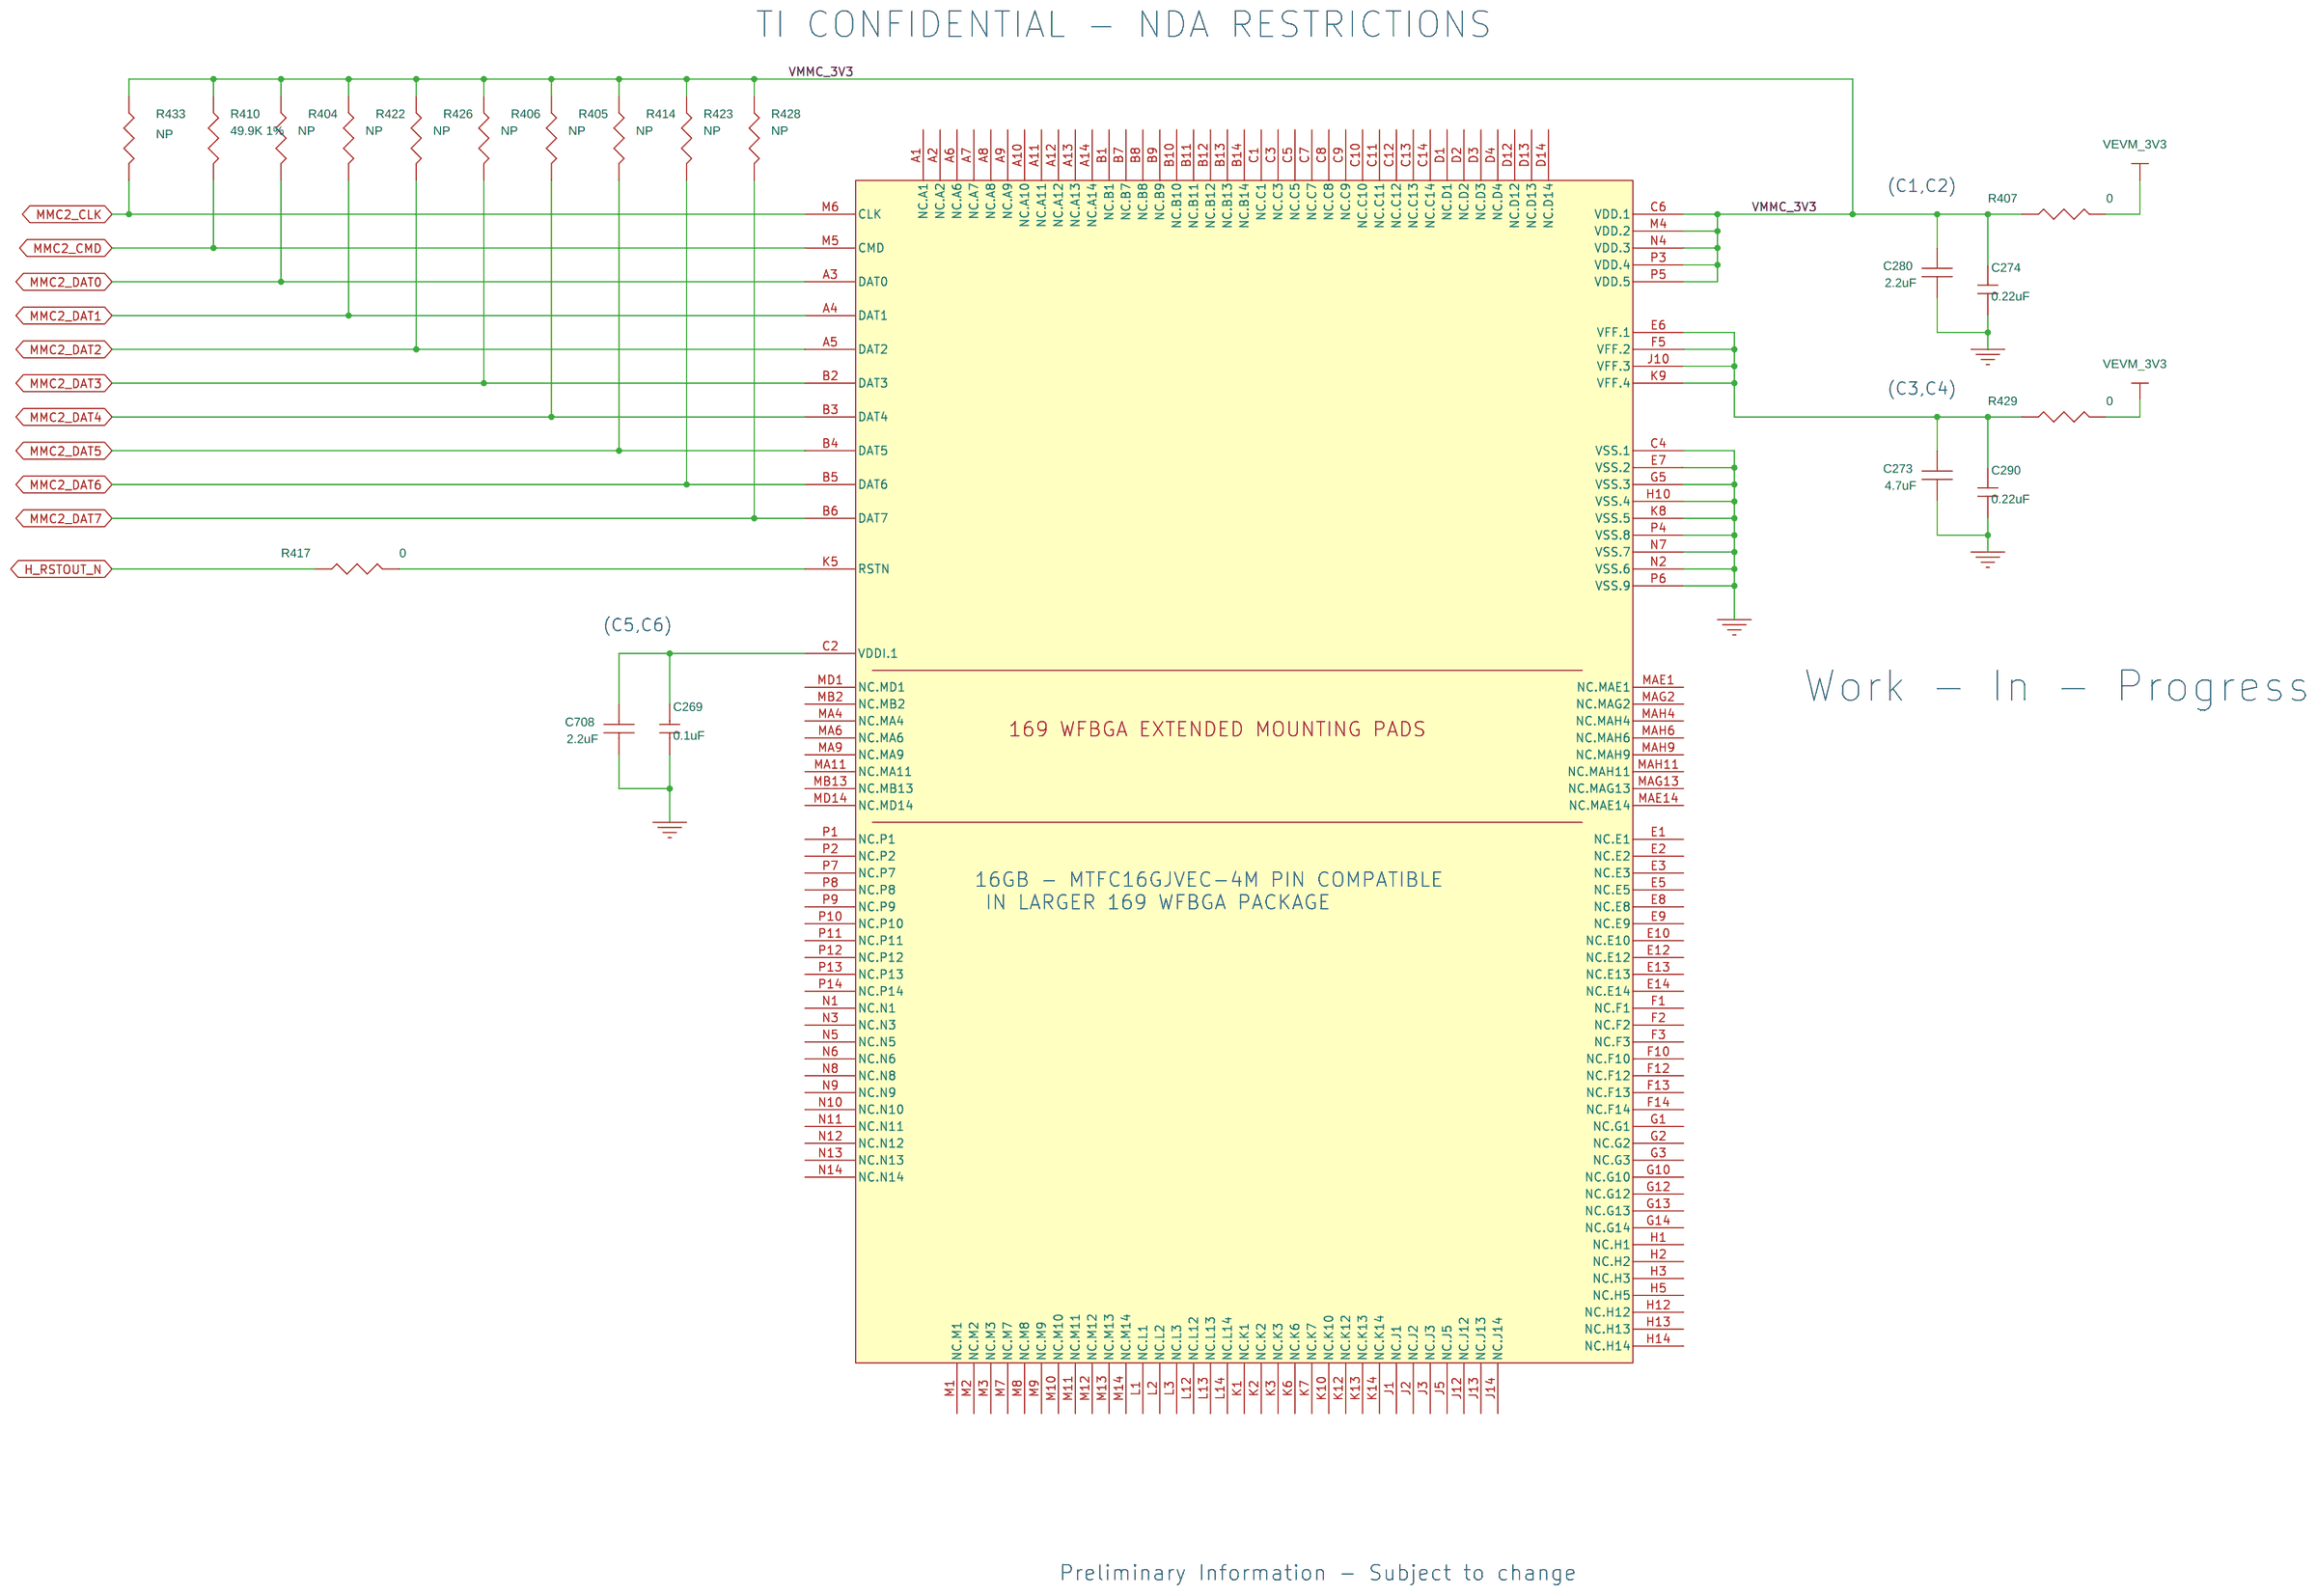
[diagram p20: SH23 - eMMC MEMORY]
22 SH24 - SPI FLASH: size B; rev: A
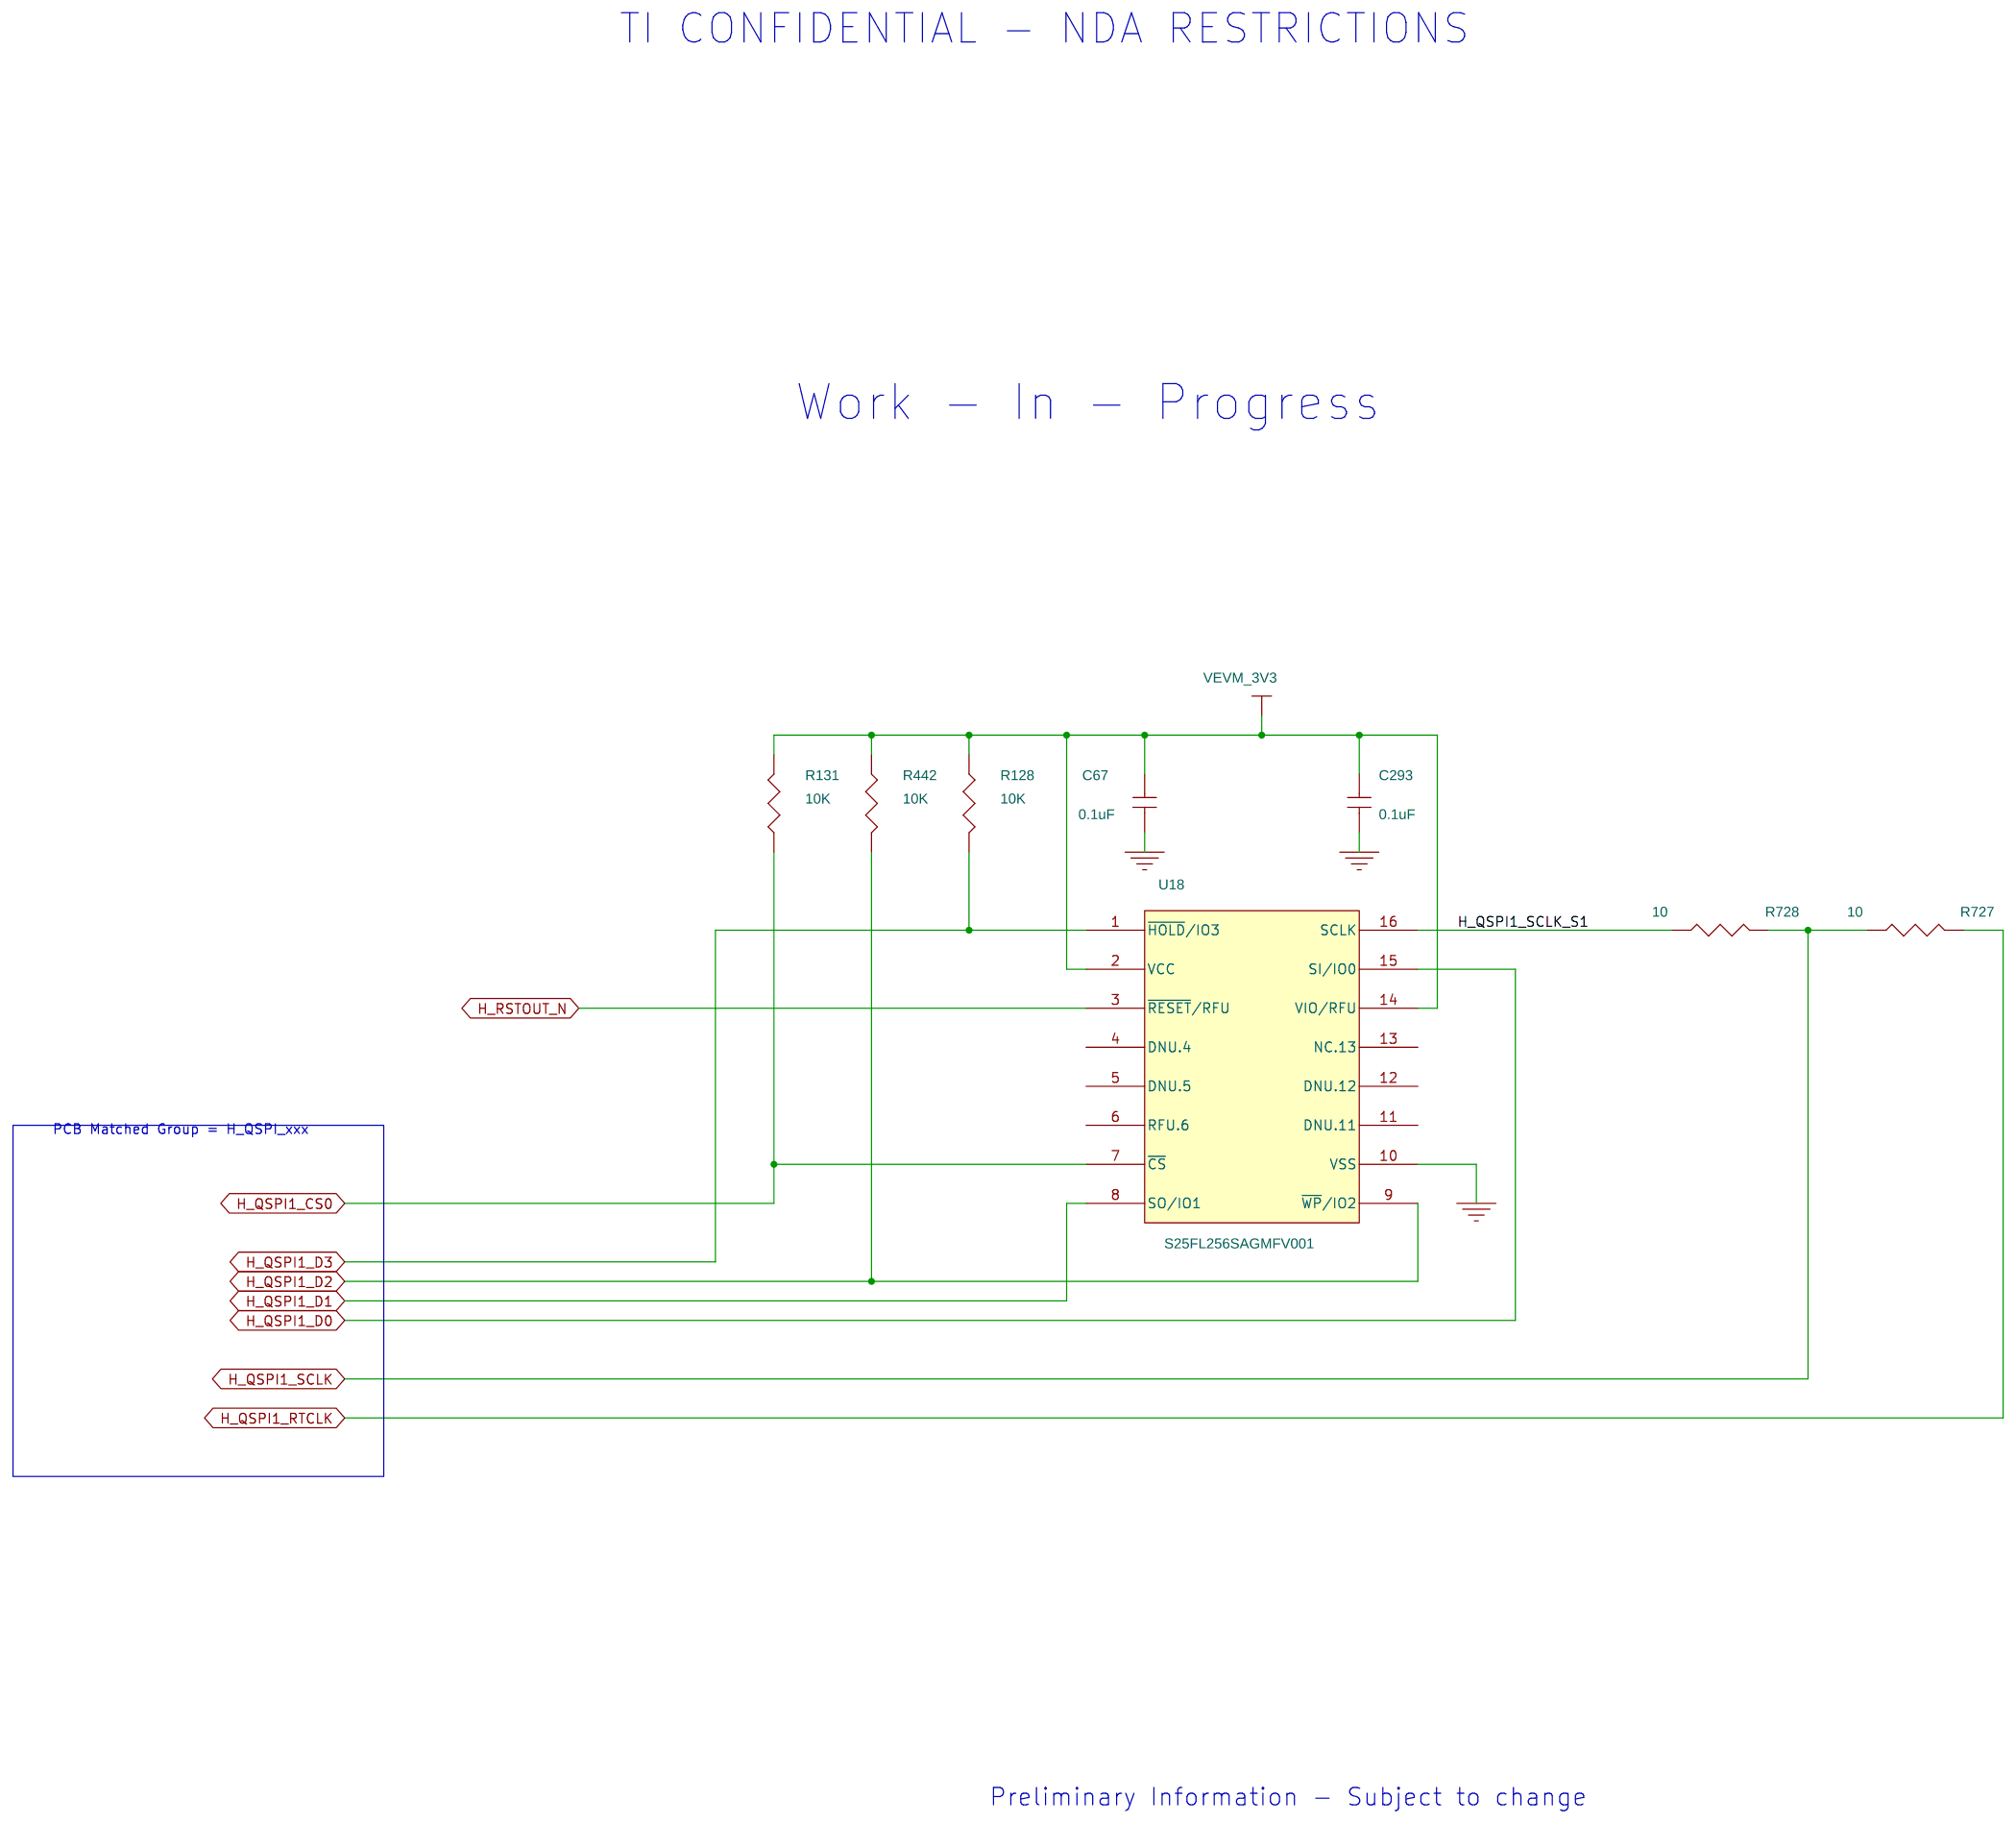
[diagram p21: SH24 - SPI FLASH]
23 SH26 - DDR3 EMIF1 TESTPOINTS: size B; rev: A
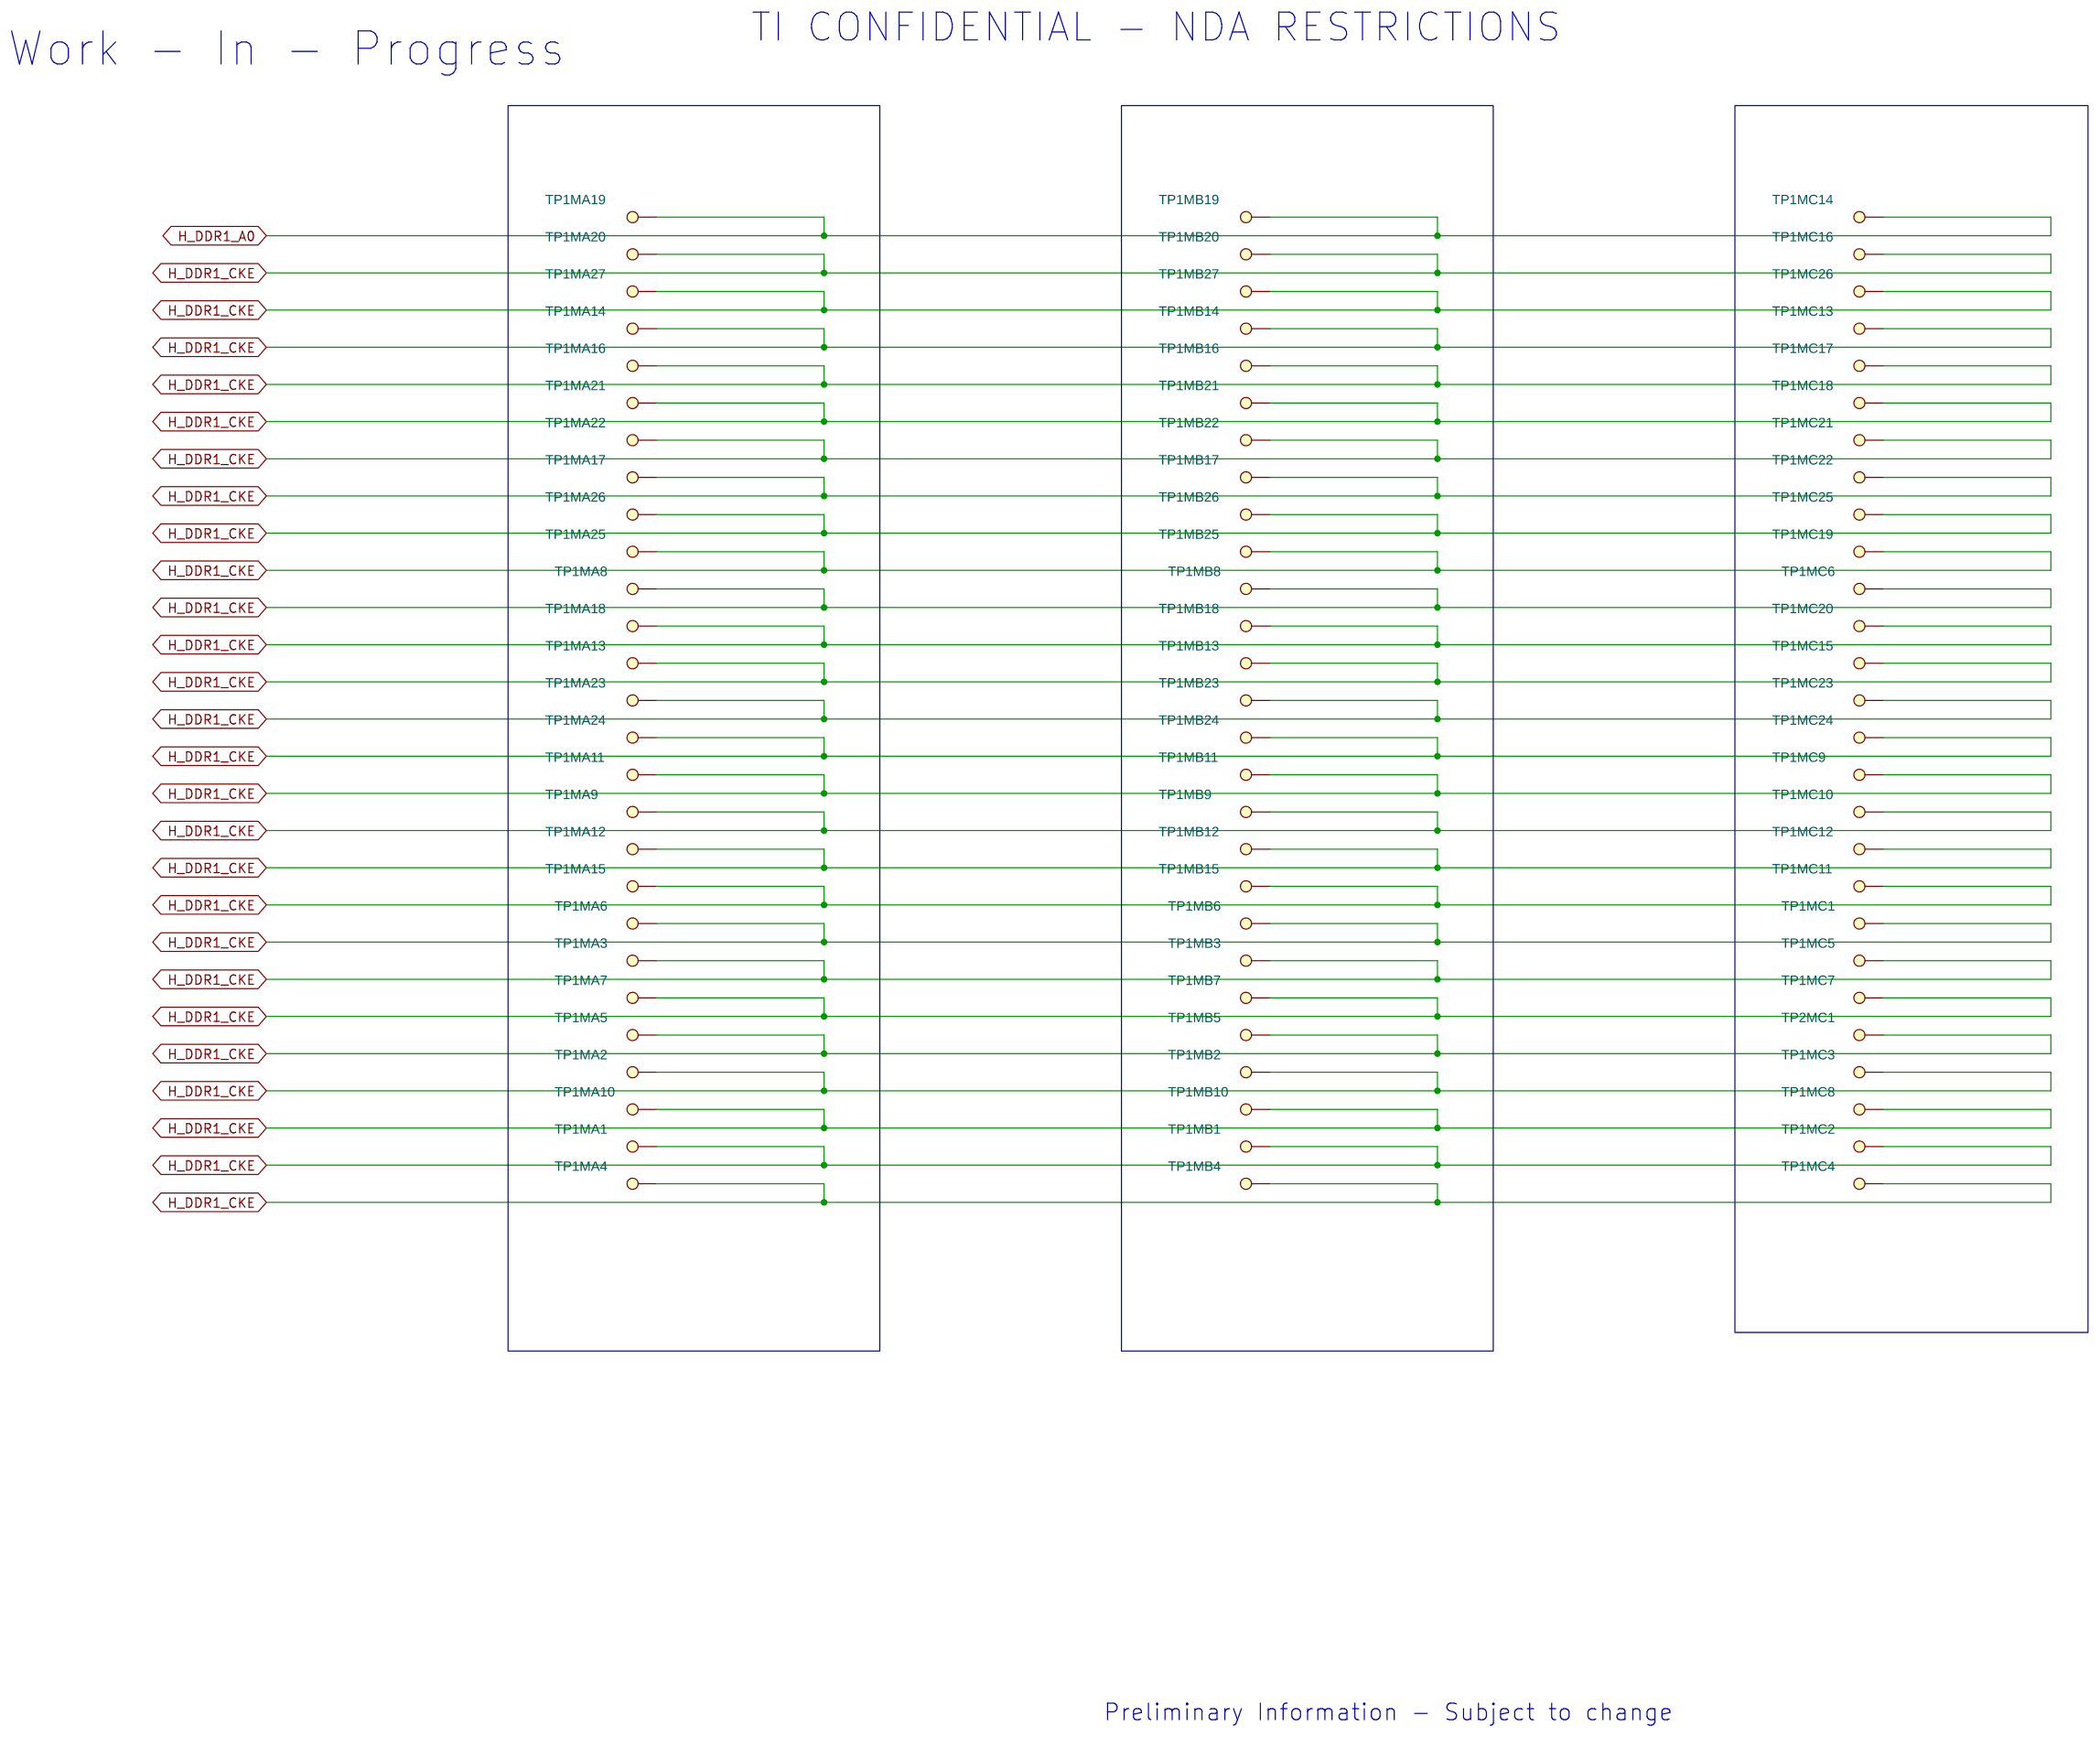
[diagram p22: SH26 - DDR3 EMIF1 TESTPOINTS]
24 SH27 - DDR3 EMIF1 BANK 1: size B; rev: A
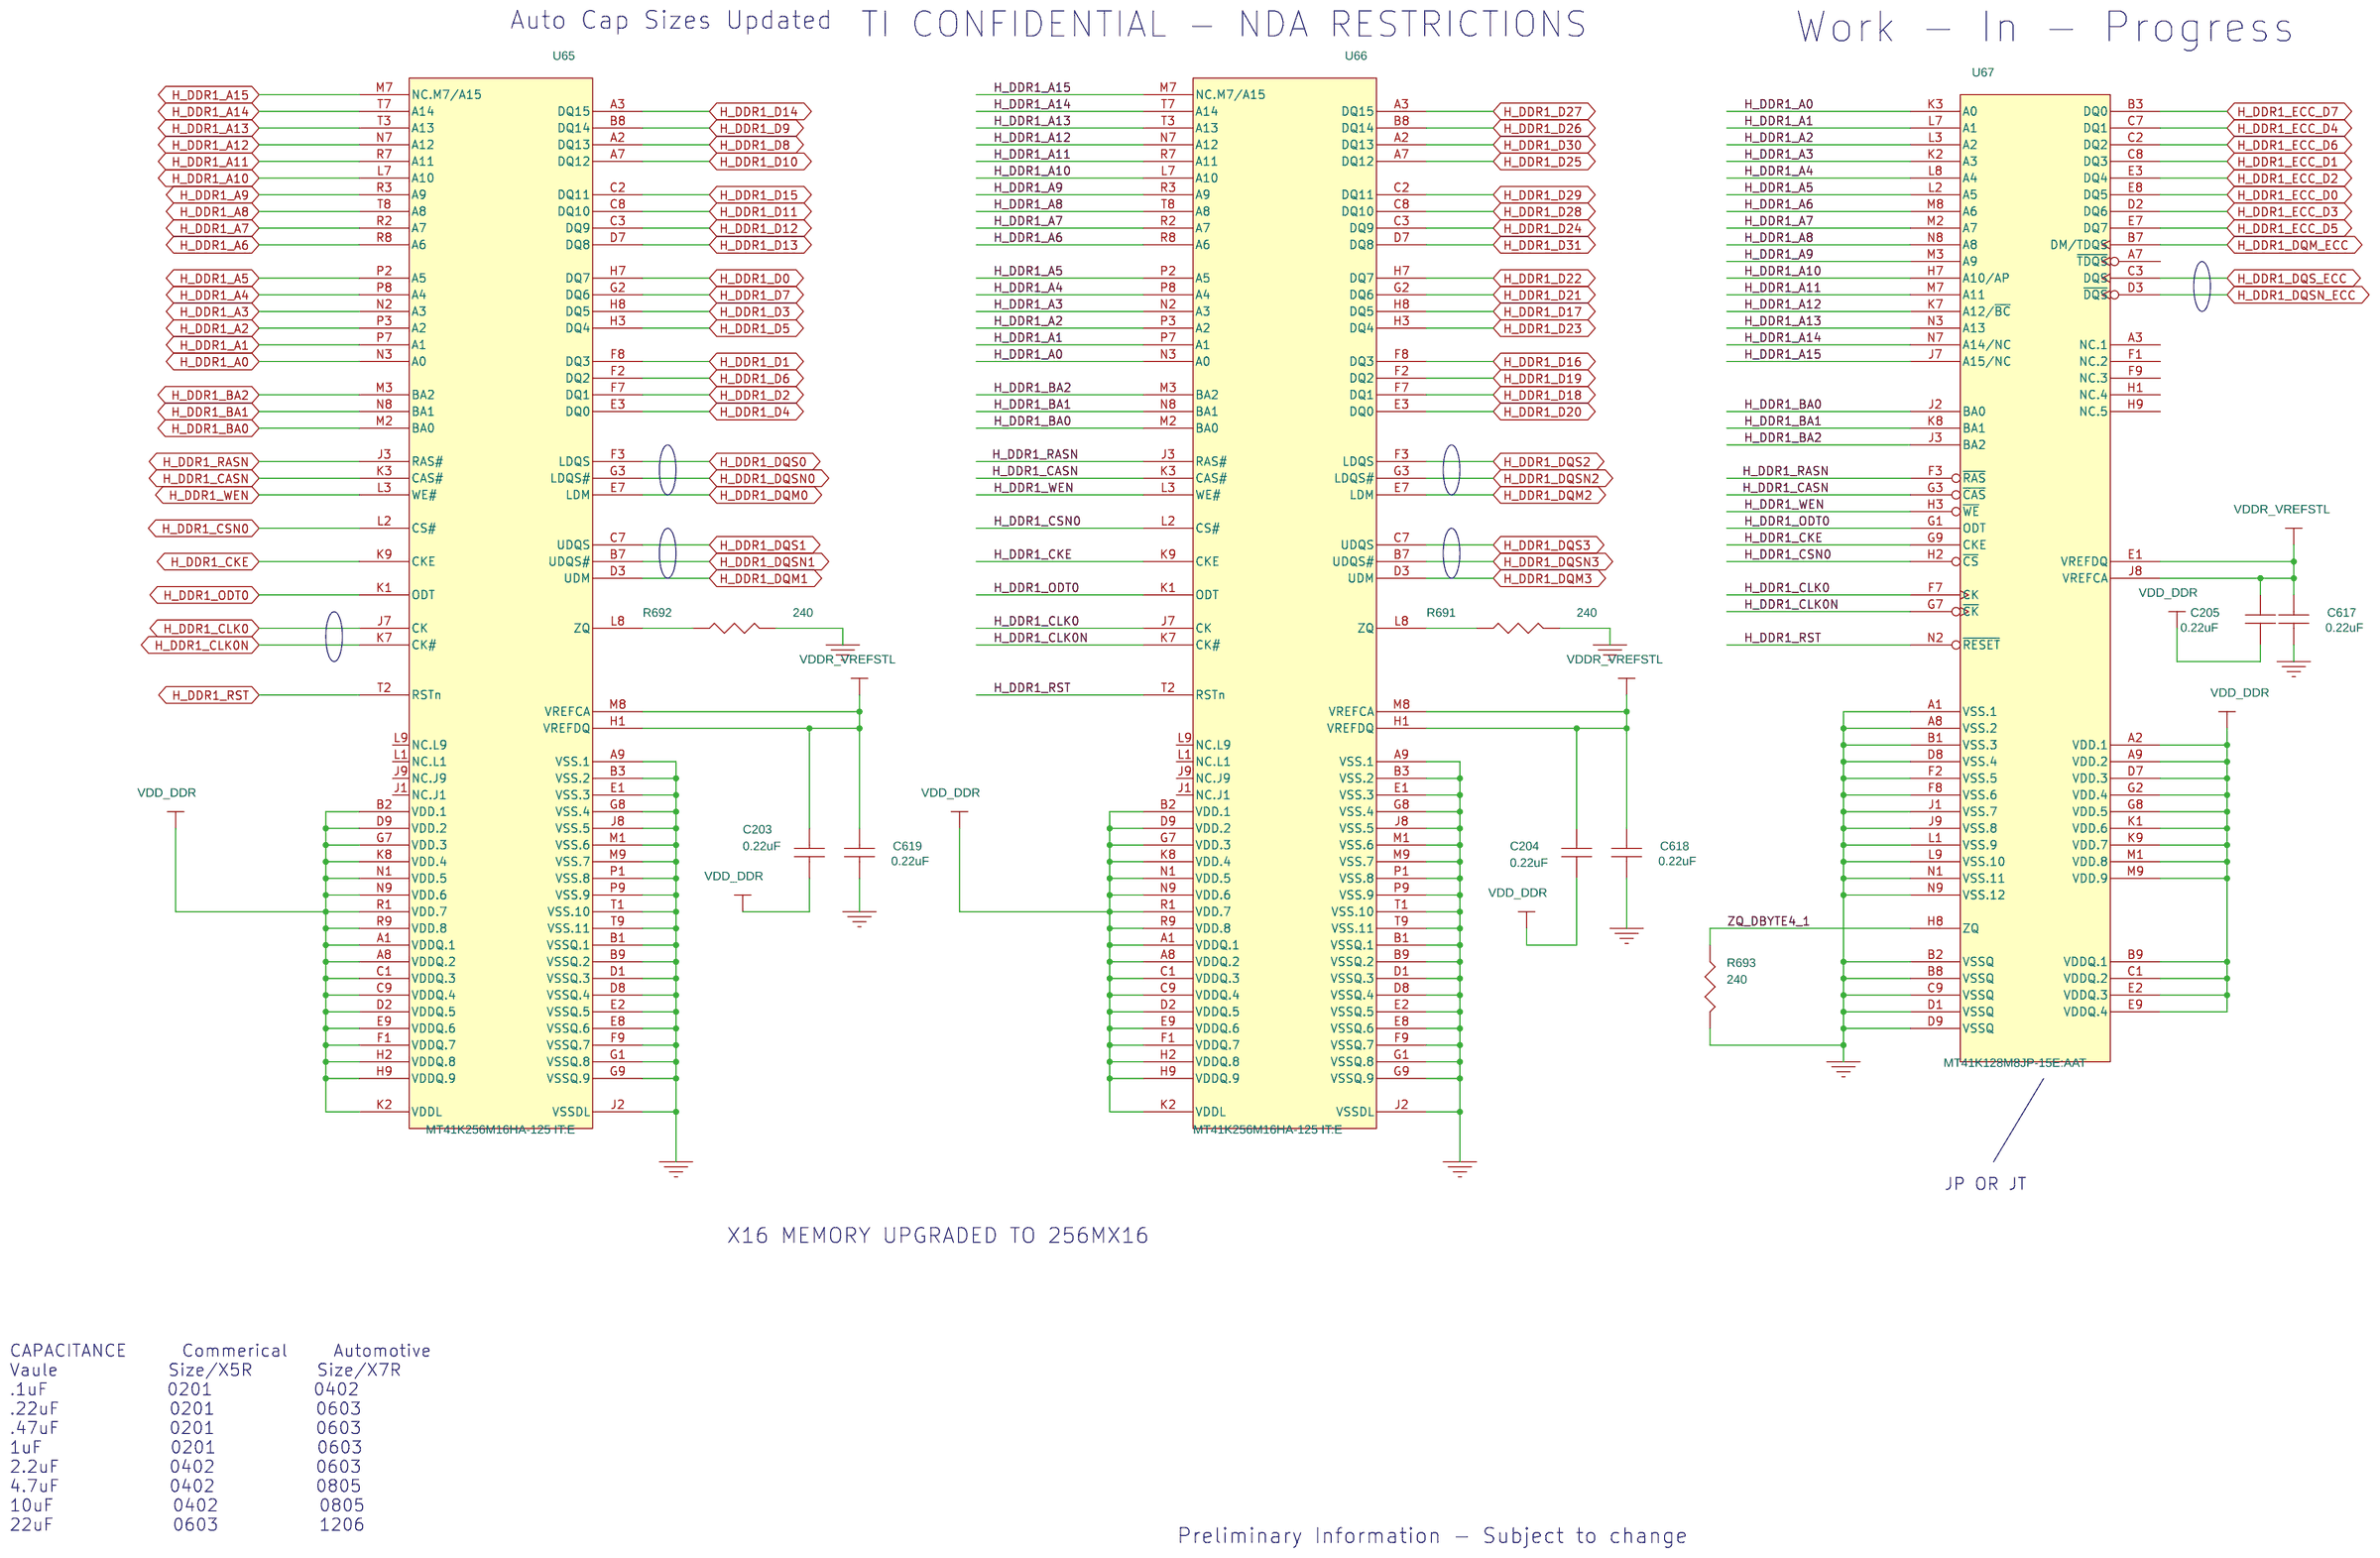
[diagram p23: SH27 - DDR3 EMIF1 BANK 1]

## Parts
sheet SH05 - VAYU ETHERNET
U52  DRA7XX  [bga-zkk-6334-p760]  (sections -1,-10,-11,-12,-13,-14,-15,-16,-17,-18,-19,-2,-20,-21,-22,-23,-3,-4,-5,-6,-7,-8,-9)
sheet SH15 - VAYU CLOCKS
C106  33pF  [c402-25]
C110  0.1uF  [c402-25]
C113  33pF  [c402-25]
C117  0.1uF  [c402-25]
C123  18 pF  [c402-25]
C124  18 pF  [c402-25]
C126  18 pF  [c402-25]
C128  18 pF  [c402-25]
C485  0.1uF  [c402-25]
C521  0.1uF  [c402-25]
C522  0.1uF  [c402-25]
C535  1000pF  [c402-25]
C550  1000pF  [c402-25]
C553  1000pF  [c402-25]
C573  0.1uF  [c402-25]
R204  NP  [r201-6p6spc]
R216  0  [r201-6p6spc]
R245  NP  [r201-6p6spc]
R256  2.2K  [r402-25]
R269  0  [r201-6p6spc]
R605  10K  [r201-6p6spc]
R620  10K  [r201-6p6spc]
R632  10K  [r201-6p6spc]
R636  10K  [r201-6p6spc]
R650  NP  [r402-25]
TP52  NP  [tp20]
TP54  NP  [tp20]
TP55  NP  [tp20]
TP57  NP  [tp20]
TP58  NP  [tp20]
TP59  NP  [tp20]
TP60  NP  [tp20]
U62  74LVC1G08DCK  [dck-5]
Y3  32.768KHz  [xtal4-23x47-ssp-t7]
Y5  22.5792MHz  [xtal4-55x87]
Y6  20MHz  [xtal2-75x94]
sheet SH16 - VAYU INTERNAL LDOS
C462  1uF  [c603-35x45]
C468  1uF  [c603-35x45]
C477  1uF  [c603-35x45]
C480  1uF  [c603-35x45]
C481  1uF  [c603-35x45]
C501  1uF  [c603-35x45]
C504  1uF  [c603-35x45]
C506  1uF  [c603-35x45]
C509  1uF  [c603-35x45]
C512  1uF  [c603-35x45]
C516  1uF  [c603-35x45]
C517  1uF  [c603-35x45]
C519  1uF  [c603-35x45]
C520  1uF  [c603-35x45]
C529  1uF  [c603-35x45]
sheet SH17 - VAYU IO POWER
C104  10uF  [c805-35x60]
C355  10uF  [c805-35x60]
C436  10uF  [c805-35x60]
C437  0.1uF  [c402-25]
C438  0.1uF  [c402-25]
C442  0.1uF  [c402-25]
C443  0.1uF  [c402-25]
C444  0.1uF  [c402-25]
C445  0.1uF  [c402-25]
C449  0.1uF  [c402-25]
C450  0.1uF  [c402-25]
C454  0.1uF  [c402-25]
C455  0.1uF  [c402-25]
C457  0.1uF  [c402-25]
C458  0.1uF  [c402-25]
C464  0.1uF  [c402-25]
C467  0.1uF  [c402-25]
C482  0.1uF  [c402-25]
C484  0.1uF  [c402-25]
C493  10uF  [c805-35x60]
C494  0.1uF  [c402-25]
C496  0.1uF  [c402-25]
C500  0.1uF  [c402-25]
C502  0.1uF  [c402-25]
C526  0.1uF  [c402-25]
C542  0.1uF  [c402-25]
C545  0.1uF  [c402-25]
sheet SH18 - VAYU 1V8 DIGITAL POWER
C357  10uF  [c805-35x60]
C371  0.1uF  [c402-25]
C382  10uF  [c805-35x60]
C399  0.1uF  [c402-25]
C400  0.1uF  [c402-25]
C401  0.1uF  [c402-25]
C402  0.1uF  [c402-25]
C406  10uF  [c805-35x60]
C461  0.1uF  [c402-25]
C471  0.1uF  [c402-25]
C518  0.1uF  [c402-25]
C524  0.1uF  [c402-25]
C530  0.1uF  [c402-25]
TP51  NP  [tp20]
sheet SH19 - VAYU DDR POWER
C136  0.22uF  [c402-25rd]
C137  0.1uF  [c402-25rd]
C138  0.1uF  [c402-25rd]
C139  0.1uF  [c402-25rd]
C140  22uF  [c402-25rd]
C143  0.1uF  [c402-25rd]
C148  0.1uF  [c402-25rd]
C541  0.1uF  [c402-25rd]
C548  0.22uF  [c402-25rd]
C556  0.22uF  [c402-25rd]
C557  0.22uF  [c402-25rd]
C559  0.1uF  [c402-25rd]
C576  1.0uF  [c402-25rd]
C577  4.7uF  [c402-25rd]
C584  0.1uF  [c402-25rd]
C656  1.0uF  [c402-25rd]
C657  4.7uF  [c402-25rd]
sheet SH20 - VAYU 1V8 ANALOG POWER
C412  0.1uF  [c402-25]
C413  0.01uF  [c402-25]
C414  0.1uF  [c402-25]
C415  0.1uF  [c402-25]
C418  1uF  [c603-35x45]
C419  0.001uF  [c402-25]
C420  0.01uF  [c402-25]
C422  0.01uF  [c402-25]
C425  0.001uF  [c402-25]
C426  1uF  [c603-35x45]
C427  0.001uF  [c402-25]
C429  1uF  [c603-35x45]
C490  1uF  [c603-35x45]
C491  0.01uF  [c402-25]
C497  0.001uF  [c402-25]
C507  0.1uF  [c402-25]
E3  NFM21PC474R1C3D  [emi-NFM21p]
E4  NFM21PC474R1C3D  [emi-NFM21p]
E5  NFM21PC474R1C3D  [emi-NFM21p]
E6  NFM21PC474R1C3D  [emi-NFM21p]
sheet SH21 - VAYU AVS POWER
C89  0.1uF  [c402-25rd]
C93  0.47uF  [c402-25rd]
C96  0.22uF  [c402-25rd]
C105  2.2uF  [c402-25rd]
C107  0.1uF  [c402-25rd]
C118  0.1uF  [c402-25rd]
C356  22uF  [c402-25rd]
C359  2.2uF  [c402-25rd]
C360  4.7uF  [c402-25rd]
C363  0.1uF  [c402-25rd]
C364  0.1uF  [c402-25rd]
C365  0.1uF  [c402-25rd]
C367  1.0uF  [c402-25rd]
C369  0.1uF  [c402-25rd]
C370  0.1uF  [c402-25rd]
C372  0.1uF  [c402-25rd]
C373  1.0uF  [c402-25rd]
C386  0.1uF  [c402-25rd]
C387  0.1uF  [c402-25rd]
C388  0.1uF  [c402-25rd]
C389  0.1uF  [c402-25rd]
C390  0.1uF  [c402-25rd]
C391  0.1uF  [c402-25rd]
C392  0.1uF  [c402-25rd]
C393  1.0uF  [c402-25rd]
C394  0.47uF  [c402-25rd]
C395  0.22uF  [c402-25rd]
C396  0.1uF  [c402-25rd]
C453  4.7uF  [c402-25rd]
C456  2.2uF  [c402-25rd]
C460  22uF  [c402-25rd]
C465  0.22uF  [c402-25rd]
C466  0.1uF  [c402-25rd]
C469  0.1uF  [c402-25rd]
C478  0.47uF  [c402-25rd]
C487  4.7uF  [c402-25rd]
C492  0.1uF  [c402-25rd]
C495  0.1uF  [c402-25rd]
C498  0.1uF  [c402-25rd]
sheet SH23 - eMMC MEMORY
C269  0.1uF  [c402-25]
C273  4.7uF  [c402-25]
C274  0.22uF  [c402-25]
C280  2.2uF  [c402-25]
C290  0.22uF  [c402-25]
C708  2.2uF  [c402-25]
R404  NP  [r402-25]
R405  NP  [r402-25]
R406  NP  [r402-25]
R407  0  [r402-25]
R410  49.9K 1%  [r402-25]
R414  NP  [r402-25]
R417  0  [r402-25]
R422  NP  [r402-25]
R423  NP  [r402-25]
R426  NP  [r402-25]
R428  NP  [r402-25]
R429  0  [r402-25]
R433  NP  [r402-25]
U121  MTFC16GJVEC-4M-169WFBGA  [fbga153-169-p5-combo]
sheet SH24 - SPI FLASH
C67  0.1uF  [c402-25]
C293  0.1uF  [c402-25]
R128  10K  [r402-25]
R131  10K  [r402-25]
R442  10K  [r402-25]
R727  10  [r402-25]
R728  10  [r402-25]
U18  S25FL256SAGMFV001  [so16-25x75-300]
sheet SH26 - DDR3 EMIF1 TESTPOINTS
TP1MA1  TP_VIA_MEM3  [tp1-18rd8]
TP1MA2  TP_VIA_MEM3  [tp1-18rd8]
TP1MA3  TP_VIA_MEM3  [tp1-18rd8]
TP1MA4  TP_VIA_MEM3  [tp1-18rd8]
TP1MA5  TP_VIA_MEM3  [tp1-18rd8]
TP1MA6  TP_VIA_MEM3  [tp1-18rd8]
TP1MA7  TP_VIA_MEM3  [tp1-18rd8]
TP1MA8  TP_VIA_MEM3  [tp1-18rd8]
TP1MA9  TP_VIA_MEM3  [tp1-18rd8]
TP1MA10  TP_VIA_MEM3  [tp1-18rd8]
TP1MA11  TP_VIA_MEM3  [tp1-18rd8]
TP1MA12  TP_VIA_MEM3  [tp1-18rd8]
TP1MA13  TP_VIA_MEM3  [tp1-18rd8]
TP1MA14  TP_VIA_MEM3  [tp1-18rd8]
TP1MA15  TP_VIA_MEM3  [tp1-18rd8]
TP1MA16  TP_VIA_MEM3  [tp1-18rd8]
TP1MA17  TP_VIA_MEM3  [tp1-18rd8]
TP1MA18  TP_VIA_MEM3  [tp1-18rd8]
TP1MA19  TP_VIA_MEM3  [tp1-18rd8]
TP1MA20  TP_VIA_MEM3  [tp1-18rd8]
TP1MA21  TP_VIA_MEM3  [tp1-18rd8]
TP1MA22  TP_VIA_MEM3  [tp1-18rd8]
TP1MA23  TP_VIA_MEM3  [tp1-18rd8]
TP1MA24  TP_VIA_MEM3  [tp1-18rd8]
TP1MA25  TP_VIA_MEM3  [tp1-18rd8]
TP1MA26  TP_VIA_MEM3  [tp1-18rd8]
TP1MA27  TP_VIA_MEM3  [tp1-18rd8]
TP1MB1  TP_VIA_MEM3  [tp1-18rd8]
TP1MB2  TP_VIA_MEM3  [tp1-18rd8]
TP1MB3  TP_VIA_MEM3  [tp1-18rd8]
TP1MB4  TP_VIA_MEM3  [tp1-18rd8]
TP1MB5  TP_VIA_MEM3  [tp1-18rd8]
TP1MB6  TP_VIA_MEM3  [tp1-18rd8]
TP1MB7  TP_VIA_MEM3  [tp1-18rd8]
TP1MB8  TP_VIA_MEM3  [tp1-18rd8]
TP1MB9  TP_VIA_MEM3  [tp1-18rd8]
TP1MB10  TP_VIA_MEM3  [tp1-18rd8]
TP1MB11  TP_VIA_MEM3  [tp1-18rd8]
TP1MB12  TP_VIA_MEM3  [tp1-18rd8]
TP1MB13  TP_VIA_MEM3  [tp1-18rd8]
TP1MB14  TP_VIA_MEM3  [tp1-18rd8]
TP1MB15  TP_VIA_MEM3  [tp1-18rd8]
TP1MB16  TP_VIA_MEM3  [tp1-18rd8]
TP1MB17  TP_VIA_MEM3  [tp1-18rd8]
TP1MB18  TP_VIA_MEM3  [tp1-18rd8]
TP1MB19  TP_VIA_MEM3  [tp1-18rd8]
TP1MB20  TP_VIA_MEM3  [tp1-18rd8]
TP1MB21  TP_VIA_MEM3  [tp1-18rd8]
TP1MB22  TP_VIA_MEM3  [tp1-18rd8]
TP1MB23  TP_VIA_MEM3  [tp1-18rd8]
TP1MB24  TP_VIA_MEM3  [tp1-18rd8]
TP1MB25  TP_VIA_MEM3  [tp1-18rd8]
TP1MB26  TP_VIA_MEM3  [tp1-18rd8]
TP1MB27  TP_VIA_MEM3  [tp1-18rd8]
TP1MC1  TP_VIA_MEM2  [tp1-18rd8]
TP1MC2  TP_VIA_MEM2  [tp1-18rd8]
TP1MC3  TP_VIA_MEM2  [tp1-18rd8]
TP1MC4  TP_VIA_MEM2  [tp1-18rd8]
TP1MC5  TP_VIA_MEM2  [tp1-18rd8]
TP1MC6  TP_VIA_MEM2  [tp1-18rd8]
TP1MC7  TP_VIA_MEM2  [tp1-18rd8]
TP1MC8  TP_VIA_MEM2  [tp1-18rd8]
TP1MC9  TP_VIA_MEM2  [tp1-18rd8]
TP1MC10  TP_VIA_MEM2  [tp1-18rd8]
TP1MC11  TP_VIA_MEM2  [tp1-18rd8]
TP1MC12  TP_VIA_MEM2  [tp1-18rd8]
TP1MC13  TP_VIA_MEM2  [tp1-18rd8]
TP1MC14  TP_VIA_MEM2  [tp1-18rd8]
TP1MC15  TP_VIA_MEM2  [tp1-18rd8]
TP1MC16  TP_VIA_MEM2  [tp1-18rd8]
TP1MC17  TP_VIA_MEM2  [tp1-18rd8]
TP1MC18  TP_VIA_MEM2  [tp1-18rd8]
TP1MC19  TP_VIA_MEM2  [tp1-18rd8]
TP1MC20  TP_VIA_MEM2  [tp1-18rd8]
TP1MC21  TP_VIA_MEM2  [tp1-18rd8]
TP1MC22  TP_VIA_MEM2  [tp1-18rd8]
TP1MC23  TP_VIA_MEM2  [tp1-18rd8]
TP1MC24  TP_VIA_MEM2  [tp1-18rd8]
TP1MC25  TP_VIA_MEM2  [tp1-18rd8]
TP1MC26  TP_VIA_MEM2  [tp1-18rd8]
TP2MC1  TP_VIA_MEM2  [tp1-18rd8]
sheet SH27 - DDR3 EMIF1 BANK 1
C203  0.22uF  [c603-35x45]
C204  0.22uF  [c603-35x45]
C205  0.22uF  [c603-35x45]
C617  0.22uF  [c603-35x45]
C618  0.22uF  [c603-35x45]
C619  0.22uF  [c603-35x45]
R691  240  [r402-25]
R692  240  [r402-25]
R693  240  [r402-25]
U65  MT41K256M16HA-125 IT:E  [bga6x16-p8-re-pkg]
U66  MT41K256M16HA-125 IT:E  [bga6x16-p8-re-pkg]
U67  MT41K128M8JP-15E:AAT  [bga6x13-p8-ra-pkg]

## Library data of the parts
U52 = VAYU_DEC_3_2: Part #: 104183-0001R
C106 C113 = Cap_18pF_Cermc_50V_5%_603_0: Part #: 101782-1334R
C110 C117 C485 C521 C522 = CAP: Part #: 103241-1100R
C123 C124 C126 C128 = CAP_NP_3: Part #: 102756-1184R
C535 C550 C553 = CAP: Part #: 103367-1102R
C573 = CAP: Part #: 101587-1100R
R204 R245 = R: Part #: R0201-NOPOP
R216 R269 = R: Part #: 103158-0001R
R256 = R: Part #: 101370-2202R
R605 R620 R632 R636 = R: Part #: 103158-1003R
R650 = R: Part #: R0402-NOPOP
TP52 TP54 TP55 TP57-TP60 = TESTPOINT: Part #: SMT-TP020
U62 = 1G08: Part #: 101057-0008R
Y3 = CRYSTAL_0: Part #: 102883-0032R
Y5 = CRYSTAL_22.5792MHz: Part #: 102740-0225R
Y6 = CRYSTAL_0_v2: Part #: 101590-0200R
C462 C468 C477 C480 C481 C501 C504 C506 C509 C512 C516 C517 C519 C520 C529 = CAP_NP: Part #: 102962-0100R
C104 C355 C357 C382 C406 C436 C493 = CAP: Part #: 102963-0101R
C399 C400 C412 C414 C415 C437 C444 C450 C455 C458 C461 C507 C518 C542 = NPCap_0: Part #: 103241-1100R
C371 C401 C402 C438 C442 C443 C445 C449 C454 C457 C464 C467 C471 C482 C484 C494 C496 C500 C502 C524 C526 C530 C545 = CAP_NP: Part #: 103241-1100R
TP51 = TestPoint1_0: Part #: SMT-TP020
C96 C136 C395 C465 C548 C556 C557 = CAP_AM_0603_0.22uf_x8l_16v_20_X
C89 C107 C118 C137-C139 C143 C148 C363-C365 C369 C370 C372 C386-C392 C396 C466 C469 C492 C495 C498 C541 C559 C584 = CAP_AM_0402_0.1uf_x7r_16v_20%_X
C140 C356 C460 = CAP_AM_1206_22uf_x7r_6.3v_20_X
C367 C373 C393 C576 C656 = CAP_AM_0603_1.0uf_x7r_16v_20_X
C360 C453 C487 C577 C657 = CAP_AM_0805_4.7uf_x7s_10v_20_X
C413 C420 C422 C491 = CAP_NP_0: Part #: 103241-1101R
C418 C426 C429 C490 = CAP_NP_0: Part #: 103214-0100R
C419 C425 C427 C497 = CAP_NP_0: Part #: 103367-1102R
E3-E6 = NFM_1: Part #: 102569-1470R
C93 C394 C478 = CAP_AM_0603_0.47uf_x7r_16v_20_X
C105 C359 C456 = CAP_AM_0603_2.2uf_x7r_6.3v_20_X
C269 = Cap_100nF_Cermc_16V_10%_603_4: Part #: 101587-1100R
C273 = CAP: Part #: 103649-0470R
C274 C290 = Cap_100nF_Cermc_16V_10%_603_4: Part #: 101587-1220R
C280 C708 = CAP: Part #: 103649-0220R
R404-R406 R414 R422 R423 R426 R428 R433 = RESISTOR: Part #: R0402-NOPOP
R407 R417 R429 = R: Part #: 101370-0001R
R410 = RESISTOR: Part #: 102145-4993R
U121 = MTFC16GJVEC-4M-169WFBGA: Part #: 104382-0016R
C67 C293 = CAP_NP: Part #: 101587-1100R
R128 R131 R442 = RESISTOR: Part #: 101370-1003R
R727 R728 = R: Part #: 101370-1000R
U18 = SPI_EEPROM_1: Part #: 104273-0001R
TP1MA1-TP1MA27 TP1MB1-TP1MB27 = TP_VIA_MEM3_0: Part #: TP-18RD8-NO-POP
TP1MC1-TP1MC26 TP2MC1 = TP_VIA_MEM2_0: Part #: TP-18RD8-NO-POP
C203 C204 C618 C619 = CAP_NP_0: Part #: 103214-1220R; SD PCB Footprint: EIA0402
C205 C617 = CAP_NP_0: Part #: 103214-1220R
R691 R692 = R_0: Part #: 101370-2401R; SD PCB Footprint: EIA0402
R693 = R: Part #: 101370-2401R
U65 U66 = DDR3_96BALL_X16_0: Part #: 104403-0125R
U67 = EDJ1108DBSE_1: Part #: 104253-0015R

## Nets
GND: C67.2 C89.2 C93.2 C96.2 C104.2 C105.2 C106.2 C107.2 C110.2 C113.2 C117.2 C118.2 C136.2 C137.2 C138.2 C139.2 C140.2 C143.2 C148.2 C269.2 C273.2 C274.2 C280.2 C290.2 C293.2 C355.2 C356.2 C357.2 C359.2 C360.2 C363.2 C364.2 C365.2 C367.2 C369.2 C370.2 C371.2 C372.2 C373.2 C382.2 C386.2 C387.2 C388.2 C389.2 C390.2 C391.2 C392.2 C393.2 C394.2 C395.2 C396.2 C399.1 C400.1 C401.2 C402.2 C406.2 C412.1 C413.2 C414.1 C415.1 C418.2 C419.2 C420.2 C422.2 C425.2 C426.2 C427.2 C429.2 C436.2 C437.1 C438.2 C442.2 C443.2 C444.1 C445.2 C449.2 C450.1 C453.2 C454.2 C455.1 C456.2 C457.2 C458.1 C460.2 C461.1 C462.2 C464.2 C465.2 C466.2 C467.2 C468.2 C469.2 C471.2 C477.2 C478.2 C480.2 C481.2 C482.2 C484.2 C485.2 C487.2 C490.2 C491.2 C492.2 C493.2 C494.2 C495.2 C496.2 C497.2 C498.2 C500.2 C501.2 C502.2 C504.2 C506.2 C507.1 C509.2 C512.2 C516.2 C517.2 C518.1 C519.2 C520.2 C521.2 C522.2 C524.2 C526.2 C529.2 C530.2 C535.2 C541.2 C542.1 C545.2 C548.2 C550.2 C553.2 C556.2 C557.2 C559.2 C573.2 C576.2 C577.2 C584.2 C617.2 C618.2 C619.2 C656.2 C657.2 C708.2 E3.2 E4.2 E5.2 E6.2 R245.2 R256.1 R620.2 R636.2 R691.2 R692.2 R693.2 U18.10(VSS) U52.A1(VSS.9) U52.A2(VSS.11) U52.A6(VSS.15) U52.A14(VSS.41) U52.A23(VSS.68) U52.A28(VSS.79) U52.AA8(VSS.17) U52.AA9(VSS.19) U52.AA10(VSS.14) U52.AA14(VSS.48) U52.AA15(VSS.51) U52.AA20(VSS.61) U52.AB14(VSS.40) U52.AB20(VSS.60) U52.AD1(VSS.3) U52.AD24(VSS.70) U52.AG1(VSS.2) U52.AH1(VSS.1) U52.AH2(VSS.10) U52.AH8(VSS.53) U52.AH20(VSS.52) U52.AH28(VSS.75) U52.B1(VSS.8) U52.D13(VSS.39) U52.D19(VSS.59) U52.E13(VSS.38) U52.E19(VSS.58) U52.F1(VSS.7) U52.F7(VSS.54) U52.G7(VSS.57) U52.G8(VSS.65) U52.G9(VSS.66) U52.H12(VSS.33) U52.J12(VSS.32) U52.J15(VSS.XX) U52.J28(VSS.78) U52.K1(VSS.6) U52.K4(VSS.12) U52.K5(VSS.13) U52.K15(VSS.28) U52.K24(VSS.55) U52.K25(VSS.56) U52.L13(VSS.37) U52.L14(VSS.46) U52.M19(VSS.69) U52.N14(VSS.X5) U52.N15(VSS.16) U52.N19(VSS.18) U52.N24(VSS.72) U52.N25(VSS.74) U52.P28(VSS.77) U52.R1(VSS.5) U52.R12(VSS.29) U52.R13(VSS.X6) U52.R15(VSS.43) U52.R21(VSS.64) U52.T10(VSS.21) U52.T11(VSS.26) U52.T12(VSS.23) U52.T14(VSS.X7) U52.T15(VSS.42) U52.T17(VSS.47) U52.T18(VSS.24) U52.T21(VSS.27) U52.U14(VSSA_VIDEO) U52.U15(VSS.X8) U52.U17(VSS.X9) U52.U20(VSS.62) U52.U21(VSS.63) U52.V15(VSS.30) U52.V17(VSS.X10) U52.W1(VSS.4) U52.W15(VSS.36) U52.W24(VSS.71) U52.W25(VSS.73) U52.W28(VSS.76) U62.3(GND) U65.A9(VSS.1) U65.B1(VSSQ.1) U65.B3(VSS.2) U65.B9(VSSQ.2) U65.D1(VSSQ.3) U65.D8(VSSQ.4) U65.E1(VSS.3) U65.E2(VSSQ.5) U65.E8(VSSQ.6) U65.F9(VSSQ.7) U65.G1(VSSQ.8) U65.G8(VSS.4) U65.G9(VSSQ.9) U65.J2(VSSDL) U65.J8(VSS.5) U65.M1(VSS.6) U65.M9(VSS.7) U65.P1(VSS.8) U65.P9(VSS.9) U65.T1(VSS.10) U65.T9(VSS.11) U66.A9(VSS.1) U66.B1(VSSQ.1) U66.B3(VSS.2) U66.B9(VSSQ.2) U66.D1(VSSQ.3) U66.D8(VSSQ.4) U66.E1(VSS.3) U66.E2(VSSQ.5) U66.E8(VSSQ.6) U66.F9(VSSQ.7) U66.G1(VSSQ.8) U66.G8(VSS.4) U66.G9(VSSQ.9) U66.J2(VSSDL) U66.J8(VSS.5) U66.M1(VSS.6) U66.M9(VSS.7) U66.P1(VSS.8) U66.P9(VSS.9) U66.T1(VSS.10) U66.T9(VSS.11) U67.A1(VSS.1) U67.A8(VSS.2) U67.B1(VSS.3) U67.B2(VSSQ) U67.B8(VSSQ) U67.C9(VSSQ) U67.D1(VSSQ) U67.D8(VSS.4) U67.D9(VSSQ) U67.F2(VSS.5) U67.F8(VSS.6) U67.J1(VSS.7) U67.J9(VSS.8) U67.L1(VSS.9) U67.L9(VSS.10) U67.N1(VSS.11) U67.N9(VSS.12) U121.C4(VSS.1) U121.E7(VSS.2) U121.G5(VSS.3) U121.H10(VSS.4) U121.K8(VSS.5) U121.N2(VSS.6) U121.N7(VSS.7) U121.P4(VSS.8) U121.P6(VSS.9) Y3.2 Y3.3 ; also on sheet 3 5 7 8 9 11 12 25 28 29 31 32 33 34 35 36 37 38 39 40 41 42 43 44 45 46 47 48 49 50 51 52 55 57
VDD_CORE: C363.1 C364.1 C386.1 C388.1 C390.1 C393.1 C394.1 C395.1 C456.1 C487.1 C498.1 U52.H13(VDD.18) U52.H14(VDD.22) U52.J17(VDD.X1) U52.J18(VDD.X2) U52.L7(VDD.34) U52.L8(VDD.15) U52.N10(VDD.6) U52.N13(VDD.16) U52.P11(VDD.9) U52.P12(VDD.12) U52.P13(VDD.X3) U52.R11(VDD.8) U52.R16(VDD.26) U52.R19(VDD.27) U52.T13(VDD.13) U52.T16(VDD.25) U52.T19(VDD.X7) U52.U8(VDD.29) U52.U9(VDD.2) U52.U13(VDD.3) U52.U16(VDD.X8) U52.V8(VDD.1) U52.V16(VDD.X9) ; also on sheet 43
VDD_DDR: C136.1 C137.1 C138.1 C139.1 C140.1 C143.1 C148.1 C203.2 C204.2 C205.2 C541.1 C548.1 C556.1 C557.1 C559.1 C576.1 C577.1 C584.1 C656.1 C657.1 U52.AA21(VDDS_DDR1.4) U52.AA22(VDDS_DDR1.2) U52.AB21(VDDS_DDR1.3) U52.AB22(VDDS_DDR1.7) U52.AB24(VDDS_DDR1.10) U52.AB25(VDDS_DDR1.11) U52.AC22(VDDS_DDR1.6) U52.AD26(VDDS_DDR1.12) U52.AG20(VDDS_DDR1.9) U52.AG28(VDDS_DDR1.5) U52.AH27(VDDS_DDR1.13) U52.E24(VDDS_DDR2.9) U52.G22(VDDS_DDR2.5) U52.G23(VDDS_DDR2.6) U52.H20(VDDS_DDR2.1) U52.H21(VDDS_DDR2.11) U52.H22(VDDS_DDR2.4) U52.J27(VDDS_DDR2.12) U52.L20(VDDS_DDR2.8) U52.L21(VDDS_DDR2.3) U52.M20(VDDS_DDR2.13) U52.M21(VDDS_DDR2.2) U52.T24(VDDS_DDR2.7) U52.T25(VDDS_DDR2.10) U52.W16(VDDS_DDR1.1) U52.W27(VDDS_DDR1.8) U65.A1(VDDQ.1) U65.A8(VDDQ.2) U65.B2(VDD.1) U65.C1(VDDQ.3) U65.C9(VDDQ.4) U65.D2(VDDQ.5) U65.D9(VDD.2) U65.E9(VDDQ.6) U65.F1(VDDQ.7) U65.G7(VDD.3) U65.H2(VDDQ.8) U65.H9(VDDQ.9) U65.K2(VDDL) U65.K8(VDD.4) U65.N1(VDD.5) U65.N9(VDD.6) U65.R1(VDD.7) U65.R9(VDD.8) U66.A1(VDDQ.1) U66.A8(VDDQ.2) U66.B2(VDD.1) U66.C1(VDDQ.3) U66.C9(VDDQ.4) U66.D2(VDDQ.5) U66.D9(VDD.2) U66.E9(VDDQ.6) U66.F1(VDDQ.7) U66.G7(VDD.3) U66.H2(VDDQ.8) U66.H9(VDDQ.9) U66.K2(VDDL) U66.K8(VDD.4) U66.N1(VDD.5) U66.N9(VDD.6) U66.R1(VDD.7) U66.R9(VDD.8) U67.A2(VDD.1) U67.A9(VDD.2) U67.B9(VDDQ.1) U67.C1(VDDQ.2) U67.D7(VDD.3) U67.E2(VDDQ.3) U67.E9(VDDQ.4) U67.G2(VDD.4) U67.G8(VDD.5) U67.K1(VDD.6) U67.K9(VDD.7) U67.M1(VDD.8) U67.M9(VDD.9) ; also on sheet 25 26 28 29 30 42 50
VDD_DSPEVE_IVA_GPU: C89.1 C105.1 C107.1 C118.1 C372.1 C373.1 C453.1 C460.1 C465.1 C466.1 C469.1 C478.1 C492.1 C495.1 U52.J13(VDD_DSPEVE.7) U52.K10(VDD_DSPEVE.8) U52.K11(VDD_DSPEVE.9) U52.K12(VDD_DSPEVE.10) U52.K13(VDD_DSPEVE.11) U52.L10(VDD_DSPEVE.2) U52.L11(VDD_DSPEVE.4) U52.L12(VDD_DSPEVE.12) U52.M10(VDD_DSPEVE.1) U52.M11(VDD_DSPEVE.5) U52.M12(VDD_DSPEVE.3) U52.M13(VDD_DSPEVE.6) U52.U11(VDD_GPU.5) U52.U12(VDD_GPU.6) U52.U18(VDD_IVA.1) U52.U19(VDD_IVA.2) U52.V10(VDD_GPU.2) U52.V11(VDD_GPU.3) U52.V14(VDD_GPU.7) U52.V18(VDD_IVA.3) U52.V19(VDD_IVA.4) U52.W10(VDD_GPU.1) U52.W11(VDD_GPU.4) U52.W13(VDD_GPU.8) ; also on sheet 42
VDD_MPU: C93.1 C96.1 C356.1 C359.1 C360.1 C365.1 C367.1 C369.1 C370.1 C387.1 C389.1 C391.1 C392.1 C396.1 U52.K17(VDD_MPU.10) U52.K18(VDD_MPU.2) U52.L15(VDD_MPU.11) U52.L16(VDD_MPU.12) U52.L17(VDD_MPU.6) U52.L18(VDD_MPU.8) U52.L19(VDD_MPU.3) U52.M15(VDD_MPU.13) U52.M16(VDD_MPU.14) U52.M17(VDD_MPU.5) U52.M18(VDD_MPU.7) U52.N17(VDD_MPU.4) U52.N18(VDD_MPU.1) U52.P17(VDD_MPU.15) U52.P18(VDD_MPU.9) U52.R18(VDD_MPU.16) ; also on sheet 42 44
VDD_RTC: C117.1 U52.AB15(VDD_RTC) ; also on sheet 41 44
VDDA_DEBUG_1V8: C414.2 C420.1 C427.1 C490.1 E4.1 U52.N11(VDDA_DEBUG) U52.N12(VDDA_DSP_EVE)
VDDA_IVA_1V8: C415.2 C422.1 C429.1 C497.1 E3.1 U52.R14(VDDA_GPU) U52.R17(VDDA_IVA)
VDDA_MPU_1V8: C413.1 C419.1 C426.1 C507.2 E5.1 U52.M14(VDDA_ABE_PER) U52.N16(VDDA_MPU)
VDDA_PLL_1V8: C521.1 C522.1 E3.3 E4.3 E5.3 E6.3 U52.AD16(VDDA_OSC.1) U52.AE16(VDDA_OSC.2) ; also on sheet 41
VDDA_RTC: C110.1 U52.AB13(VDDA_RTC) ; also on sheet 41
VDDA_VIDEO_1V8: C412.2 C418.1 C425.1 C491.1 E6.1 U52.P14(VDDA_VIDEO) U52.P15(VDDA_GMAC_CORE) U52.P16(VDDA_DDR)
VDDR_VREFSTL: C203.1 C204.1 C205.1 C617.1 C618.1 C619.1 U65.H1(VREFDQ) U65.M8(VREFCA) U66.H1(VREFDQ) U66.M8(VREFCA) U67.E1(VREFDQ) U67.J8(VREFCA) ; also on sheet 7 8 28 50
VDDS_1V8: C357.1 C371.1 C382.1 C399.2 C400.2 C401.1 C402.1 C406.1 C461.2 C471.1 C518.2 C524.1 C530.1 U52.AA18(VDDS18V_DDR1.1) U52.AA19(VDDS18V_DDR1.2) U52.G18(VDDS18V.8) U52.H17(VDDS18V.11) U52.J21(VDDS18V_DDR2.3) U52.J22(VDDS18V_DDR2.4) U52.M8(VDDS18V.9) U52.M9(VDDS18V.7) U52.N8(VDDS18V.4) U52.N21(VDDS18V_DDR2.2) U52.P8(VDDS18V.5) U52.P20(VDDS18V_DDR2.5) U52.P21(VDDS18V_DDR2.1) U52.R8(VDDS18V.3) U52.T8(VDDS18V.2) U52.V21(VDDS18V.12) U52.V22(VDDS18V.6) U52.W17(VDDS18V.10) U52.W18(VDDS18V.1) U52.W21(VDDS18V_DDR1.4) U52.Y21(VDDS18V_DDR1.3) ; also on sheet 9 43
VDDSHV: C104.1 C355.1 C436.1 C437.2 C438.1 C442.1 C443.1 C444.2 C445.1 C449.1 C450.2 C454.1 C455.2 C457.1 C458.2 C464.1 C482.1 C484.1 C493.1 C494.1 C496.1 C500.1 C502.1 C526.1 C542.2 C545.1 U52.AB6(VDDSHV7.1) U52.AB7(VDDSHV7.2) U52.AD5(VDDSHV6.2) U52.AD7(VDDSHV6.4) U52.AE7(VDDSHV6.3) U52.AF5(VDDSHV6.1) U52.B6(VDDSHV2.1) U52.B23(VDDSHV3.9) U52.C24(VDDSHV4.1) U52.D10(VDDSHV2.5) U52.D16(VDDSHV3.4) U52.D22(VDDSHV3.8) U52.E3(VDDSHV1.1) U52.E5(VDDSHV1.4) U52.E10(VDDSHV2.4) U52.E16(VDDSHV3.3) U52.E22(VDDSHV3.7) U52.G4(VDDSHV1.2) U52.G5(VDDSHV1.3) U52.G15(VDDSHV3.2) U52.H8(VDDSHV1.5) U52.H9(VDDSHV1.6) U52.H10(VDDSHV2.2) U52.H11(VDDSHV2.3) U52.H15(VDDSHV3.1) U52.H16(VDDSHV3.6) U52.H18(VDDSHV3.5) U52.H19(VDDSHV3.10) U52.J8(VDDSHV11.2) U52.K8(VDDSHV11.1) U52.N4(VDDSHV10.2) U52.N5(VDDSHV10.4) U52.P10(VDDSHV10.6) U52.R7(VDDSHV10.5) U52.R10(VDDSHV10.7) U52.T4(VDDSHV10.1) U52.T5(VDDSHV10.3) U52.U10(VDDSHV9.3) U52.W4(VDDSHV9.1) U52.W5(VDDSHV9.2) ; also on sheet 49
VDDSHV5: C485.1 R204.1 R605.2 U52.V12(VDDSHV5) ; also on sheet 41 44 55
VDDSHV8: C467.1 U52.W8(VDDSHV8.2) U52.Y8(VDDSHV8.1) ; also on sheet 41
CPU_POR_RESETn: U62.2(A) ; also on sheet 44
H_DDR1_A0: TP1MA19.1 TP1MB19.1 TP1MC14.1 U65.N3(A0) U66.N3(A0) U67.K3(A0) ; also on sheet 7 26
H_DDR1_A1: U65.P7(A1) U66.P7(A1) U67.L7(A1) ; also on sheet 7 26
H_DDR1_A2: U65.P3(A2) U66.P3(A2) U67.L3(A2) ; also on sheet 7 26
H_DDR1_A3: U65.N2(A3) U66.N2(A3) U67.K2(A3) ; also on sheet 7 26
H_DDR1_A4: U65.P8(A4) U66.P8(A4) U67.L8(A4) ; also on sheet 7 26
H_DDR1_A5: U65.P2(A5) U66.P2(A5) U67.L2(A5) ; also on sheet 7 26
H_DDR1_A6: U65.R8(A6) U66.R8(A6) U67.M8(A6) ; also on sheet 7 26
H_DDR1_A7: U65.R2(A7) U66.R2(A7) U67.M2(A7) ; also on sheet 7 26
H_DDR1_A8: U65.T8(A8) U66.T8(A8) U67.N8(A8) ; also on sheet 7 26
H_DDR1_A9: U65.R3(A9) U66.R3(A9) U67.M3(A9) ; also on sheet 7 26
H_DDR1_A10: U65.L7(A10) U66.L7(A10) U67.H7(A10/AP) ; also on sheet 7 26
H_DDR1_A11: U65.R7(A11) U66.R7(A11) U67.M7(A11) ; also on sheet 7 26
H_DDR1_A12: U65.N7(A12) U66.N7(A12) U67.K7(A12/~{BC}) ; also on sheet 7 26
H_DDR1_A13: U65.T3(A13) U66.T3(A13) U67.N3(A13) ; also on sheet 7 26
H_DDR1_A14: U65.T7(A14) U66.T7(A14) U67.N7(A14/NC) ; also on sheet 7 26
H_DDR1_A15: U65.M7(NC.M7/A15) U66.M7(NC.M7/A15) U67.J7(A15/NC) ; also on sheet 7 26
H_DDR1_BA0: U65.M2(BA0) U66.M2(BA0) U67.J2(BA0) ; also on sheet 7 26
H_DDR1_BA1: U65.N8(BA1) U66.N8(BA1) U67.K8(BA1) ; also on sheet 7 26
H_DDR1_BA2: U65.M3(BA2) U66.M3(BA2) U67.J3(BA2) ; also on sheet 7 26
H_DDR1_CASN: U65.K3(CAS#) U66.K3(CAS#) U67.G3(~{CAS}) ; also on sheet 7 26
H_DDR1_CKE: TP1MA1.1 TP1MA2.1 TP1MA3.1 TP1MA4.1 TP1MA5.1 TP1MA6.1 TP1MA7.1 TP1MA8.1 TP1MA9.1 TP1MA10.1 TP1MA11.1 TP1MA12.1 TP1MA13.1 TP1MA14.1 TP1MA15.1 TP1MA16.1 TP1MA17.1 TP1MA18.1 TP1MA20.1 TP1MA21.1 TP1MA22.1 TP1MA23.1 TP1MA24.1 TP1MA25.1 TP1MA26.1 TP1MA27.1 TP1MB1.1 TP1MB2.1 TP1MB3.1 TP1MB4.1 TP1MB5.1 TP1MB6.1 TP1MB7.1 TP1MB8.1 TP1MB9.1 TP1MB10.1 TP1MB11.1 TP1MB12.1 TP1MB13.1 TP1MB14.1 TP1MB15.1 TP1MB16.1 TP1MB17.1 TP1MB18.1 TP1MB20.1 TP1MB21.1 TP1MB22.1 TP1MB23.1 TP1MB24.1 TP1MB25.1 TP1MB26.1 TP1MB27.1 TP1MC1.1 TP1MC2.1 TP1MC3.1 TP1MC4.1 TP1MC5.1 TP1MC6.1 TP1MC7.1 TP1MC8.1 TP1MC9.1 TP1MC10.1 TP1MC11.1 TP1MC12.1 TP1MC13.1 TP1MC15.1 TP1MC16.1 TP1MC17.1 TP1MC18.1 TP1MC19.1 TP1MC20.1 TP1MC21.1 TP1MC22.1 TP1MC23.1 TP1MC24.1 TP1MC25.1 TP1MC26.1 TP2MC1.1 U65.K9(CKE) U66.K9(CKE) U67.G9(CKE) ; also on sheet 7 26
H_DDR1_CLK0: U65.J7(CK) U66.J7(CK) U67.F7(CK) ; also on sheet 7 26
H_DDR1_CLK0N: U65.K7(CK#) U66.K7(CK#) U67.G7(~{CK}) ; also on sheet 7 26
H_DDR1_CSN0: U65.L2(CS#) U66.L2(CS#) U67.H2(~{CS}) ; also on sheet 7 26
H_DDR1_D0: U65.H7(DQ7) ; also on sheet 7
H_DDR1_D1: U65.F8(DQ3) ; also on sheet 7
H_DDR1_D2: U65.F7(DQ1) ; also on sheet 7
H_DDR1_D3: U65.H8(DQ5) ; also on sheet 7
H_DDR1_D4: U65.E3(DQ0) ; also on sheet 7
H_DDR1_D5: U65.H3(DQ4) ; also on sheet 7
H_DDR1_D6: U65.F2(DQ2) ; also on sheet 7
H_DDR1_D7: U65.G2(DQ6) ; also on sheet 7
H_DDR1_D8: U65.A2(DQ13) ; also on sheet 7
H_DDR1_D9: U65.B8(DQ14) ; also on sheet 7
H_DDR1_D10: U65.A7(DQ12) ; also on sheet 7
H_DDR1_D11: U65.C8(DQ10) ; also on sheet 7
H_DDR1_D12: U65.C3(DQ9) ; also on sheet 7
H_DDR1_D13: U65.D7(DQ8) ; also on sheet 7
H_DDR1_D14: U65.A3(DQ15) ; also on sheet 7
H_DDR1_D15: U65.C2(DQ11) ; also on sheet 7
H_DDR1_D16: U66.F8(DQ3) ; also on sheet 7
H_DDR1_D17: U66.H8(DQ5) ; also on sheet 7
H_DDR1_D18: U66.F7(DQ1) ; also on sheet 7
H_DDR1_D19: U66.F2(DQ2) ; also on sheet 7
H_DDR1_D20: U66.E3(DQ0) ; also on sheet 7
H_DDR1_D21: U66.G2(DQ6) ; also on sheet 7
H_DDR1_D22: U66.H7(DQ7) ; also on sheet 7
H_DDR1_D23: U66.H3(DQ4) ; also on sheet 7
H_DDR1_D24: U66.C3(DQ9) ; also on sheet 7
H_DDR1_D25: U66.A7(DQ12) ; also on sheet 7
H_DDR1_D26: U66.B8(DQ14) ; also on sheet 7
H_DDR1_D27: U66.A3(DQ15) ; also on sheet 7
H_DDR1_D28: U66.C8(DQ10) ; also on sheet 7
H_DDR1_D29: U66.C2(DQ11) ; also on sheet 7
H_DDR1_D30: U66.A2(DQ13) ; also on sheet 7
H_DDR1_D31: U66.D7(DQ8) ; also on sheet 7
H_DDR1_DQM0: U65.E7(LDM) ; also on sheet 7
H_DDR1_DQM1: U65.D3(UDM) ; also on sheet 7
H_DDR1_DQM2: U66.E7(LDM) ; also on sheet 7
H_DDR1_DQM3: U66.D3(UDM) ; also on sheet 7
H_DDR1_DQM_ECC: U67.B7(DM/TDQS) ; also on sheet 7
H_DDR1_DQS0: U65.F3(LDQS) ; also on sheet 7
H_DDR1_DQS1: U65.C7(UDQS) ; also on sheet 7
H_DDR1_DQS2: U66.F3(LDQS) ; also on sheet 7
H_DDR1_DQS3: U66.C7(UDQS) ; also on sheet 7
H_DDR1_DQS_ECC: U67.C3(DQS) ; also on sheet 7
H_DDR1_DQSN0: U65.G3(LDQS#) ; also on sheet 7
H_DDR1_DQSN1: U65.B7(UDQS#) ; also on sheet 7
H_DDR1_DQSN2: U66.G3(LDQS#) ; also on sheet 7
H_DDR1_DQSN3: U66.B7(UDQS#) ; also on sheet 7
H_DDR1_DQSN_ECC: U67.D3(~{DQS}) ; also on sheet 7
H_DDR1_ECC_D0: U67.E8(DQ5) ; also on sheet 7
H_DDR1_ECC_D1: U67.C8(DQ3) ; also on sheet 7
H_DDR1_ECC_D2: U67.E3(DQ4) ; also on sheet 7
H_DDR1_ECC_D3: U67.D2(DQ6) ; also on sheet 7
H_DDR1_ECC_D4: U67.C7(DQ1) ; also on sheet 7
H_DDR1_ECC_D5: U67.E7(DQ7) ; also on sheet 7
H_DDR1_ECC_D6: U67.C2(DQ2) ; also on sheet 7
H_DDR1_ECC_D7: U67.B3(DQ0) ; also on sheet 7
H_DDR1_ODT0: U65.K1(ODT) U66.K1(ODT) U67.G1(ODT) ; also on sheet 7 26
H_DDR1_RASN: U65.J3(RAS#) U66.J3(RAS#) U67.F3(~{RAS}) ; also on sheet 7 26
H_DDR1_RST: U65.T2(RSTn) U66.T2(RSTn) U67.N2(~{RESET}) ; also on sheet 7
H_DDR1_WEN: U65.L3(WE#) U66.L3(WE#) U67.H3(~{WE}) ; also on sheet 7 26
H_NMIN: R245.1 R632.2 U52.D21(NMIN)
H_ON_OFF: R216.2 U52.Y11(ON_OFF)
H_OSC0_RTN: C126.2 C128.2 U52.AF15(VSSA_OSC0)
H_OSC0_XIN: C128.1 U52.AE15(XI_OSC0) Y6.1
H_OSC0_XOUT: C126.1 U52.AD15(X0_OSC0) Y6.2
H_OSC1_RTN: C123.2 C124.2 U52.AC14(VSSA_OSC1) Y5.2 Y5.4
H_OSC1_XIN: C123.1 U52.AC15(XI_OSC1) Y5.1
H_OSC1_XOUT: C124.1 U52.AC13(XO_OSC1) Y5.3
H_OSCRTC_XIN: C113.1 U52.AE14(RTC_OSC_XI_CLKIN32) Y3.4
H_OSCRTC_XOUT: C106.1 U52.AD14(RTC_OSC_XO) Y3.1
H_POR_N: C550.1 R269.2 TP60.1(TP) U52.F22(PORZ) U62.4(Y)
H_QSPI1_CS0: R131.1 U18.7(~{CS})
H_QSPI1_D0: U18.15(SI/IO0) ; also on sheet 6
H_QSPI1_D1: U18.8(SO/IO1) ; also on sheet 6
H_QSPI1_D2: R442.2 U18.9(~{WP}/IO2) ; also on sheet 6
H_QSPI1_D3: R128.2 U18.1(~{HOLD}/IO3) ; also on sheet 6
H_QSPI1_RTCLK: R727.2 ; also on sheet 6
H_QSPI1_SCLK (page SH24 - SPI FLASH): R727.1 R728.2
H_QSPI1_SCLK_S1 (page SH24 - SPI FLASH): R728.1 U18.16(SCLK)
H_RESET_N: C553.1 TP59.1(TP) U52.E23(RESETN)
H_RSTOUT_N: R256.2 R417.1 R650.2 TP58.1(TP) U18.3(~{RESET}/RFU) U52.F23(RSTOUTN) ; also on sheet 38 39 46 52
H_WAKEUP0: TP54.1(TP) U52.AD17(WAKEUP0)
H_WAKEUP2: C535.1 R636.1 TP52.1(TP) U52.AB16(WAKEUP2)
H_WAKEUP3: R620.1 TP55.1(TP) U52.AC16(WAKEUP3)
MMC2_CLK: R433.2 U121.M6(CLK)
MMC2_CMD: R410.2 U121.M5(CMD)
MMC2_DAT0: R404.2 U121.A3(DAT0)
MMC2_DAT1: R422.2 U121.A4(DAT1)
MMC2_DAT2: R426.2 U121.A5(DAT2)
MMC2_DAT3: R406.2 U121.B2(DAT3)
MMC2_DAT4: R405.2 U121.B3(DAT4)
MMC2_DAT5: R414.2 U121.B4(DAT5)
MMC2_DAT6: R423.2 U121.B5(DAT6)
MMC2_DAT7: R428.2 U121.B6(DAT7)
PMIC_INT: R605.1 TP57.1(TP) U52.AC17(WAKEUP1) ; also on sheet 40
PMIC_OFF: R204.2 R216.1 ; also on sheet 40 55
PMIC_RESET_OUT: U62.1(B) ; also on sheet 40
RTC_PORZ: U52.AB17(RTC_PORZ) ; also on sheet 44
VCAP_VBBLDO_DSPEVE: C477.1 U52.K9(CAP_VBBLDO_DSPEVE)
VCAP_VBBLDO_GPU: C501.1 U52.Y14(CAP_VBBLDO_GPU)
VCAP_VBBLDO_IVA: C519.1 U52.R20(CAP_VBBLDO_IVA)
VCAP_VBBLDO_MPU: C509.1 U52.J16(CAP_VBBLDO_MPU)
VCAP_VDDRAM_CORE1: C468.1 U52.L9(CAP_VDDRAM_CORE1)
VCAP_VDDRAM_CORE2: C517.1 U52.J19(CAP_VDDRAM_CORE2)
VCAP_VDDRAM_CORE3: C506.1 U52.Y15(CAP_VDDRAM_CORE3)
VCAP_VDDRAM_CORE4: C516.1 U52.P19(CAP_VDDRAM_CORE4)
VCAP_VDDRAM_CORE5: C512.1 U52.Y16(CAP_VDDRAM_CORE5)
VCAP_VDDRAM_DSPEVE1: C481.1 U52.J10(CAP_VDDRAM_DSPEVE1)
VCAP_VDDRAM_DSPEVE2: C462.1 U52.J9(CAP_VDDRAM_DSPEVE2)
VCAP_VDDRAM_GPU: C480.1 U52.Y13(CAP_VDDRAM_GPU)
VCAP_VDDRAM_IVA: C529.1 U52.T20(CAP_VDDRAM_IVA)
VCAP_VDDRAM_MPU1: C504.1 U52.K16(CAP_VDDRAM_MPU1)
VCAP_VDDRAM_MPU2: C520.1 U52.K19(CAP_VDDRAM_MPU2)
VEVM_3V3: C67.1 C293.1 C573.1 R128.1 R131.2 R407.2 R429.2 R442.1 R632.1 R650.1 U18.2(VCC) U18.14(VIO/RFU) U62.5(VCC) ; also on sheet 3 12 31 32 33 34 35 37 38 40 41 42 43 44 45 46 48 49 51 52 55 56 57
VMMC_3V3: C274.1 C280.1 R404.1 R405.1 R406.1 R407.1 R410.1 R414.1 R422.1 R423.1 R426.1 R428.1 R433.1 U121.C6(VDD.1) U121.M4(VDD.2) U121.N4(VDD.3) U121.P3(VDD.4) U121.P5(VDD.5)
VPP: TP51.1 U52.K14(VPP)
ZQ_DBYTE4_1: R693.1 U67.H8(ZQ)
N35610: R692.1 U65.L8(ZQ)
N35614: R691.1 U66.L8(ZQ)
N21391032: R417.2 U121.K5(RSTN)
N21391113: C269.1 C708.1 U121.C2(VDDI.1)
N21391608: C273.1 C290.1 R429.1 U121.E6(VFF.1) U121.F5(VFF.2) U121.J10(VFF.3) U121.K9(VFF.4)
N27151094: R269.1 U52.AF14(RTC_ISO)

Not connected (* = marked no-connect by the designer): U18 4(DNU.4) 5(DNU.5) 6(RFU.6) 11(DNU.11) 12(DNU.12) 13(NC.13); U52 A27(IFORCE)* B28(VSENSE)* Y10(ATESTV)*; U65 J1(NC.J1) J9(NC.J9) L1(NC.L1) L9(NC.L9); U66 J1(NC.J1) J9(NC.J9) L1(NC.L1) L9(NC.L9); U67 A3(NC.1) A7(~{TDQS}) F1(NC.2) F9(NC.3) H1(NC.4) H9(NC.5); U121 A1(NC.A1) A2(NC.A2) A6(NC.A6) A7(NC.A7) A8(NC.A8) A9(NC.A9) A10(NC.A10) A11(NC.A11) A12(NC.A12) A13(NC.A13) A14(NC.A14) B1(NC.B1) B7(NC.B7) B8(NC.B8) B9(NC.B9) B10(NC.B10) B11(NC.B11) B12(NC.B12) B13(NC.B13) B14(NC.B14) C1(NC.C1) C3(NC.C3) C5(NC.C5) C7(NC.C7) C8(NC.C8) C9(NC.C9) C10(NC.C10) C11(NC.C11) C12(NC.C12) C13(NC.C13) C14(NC.C14) D1(NC.D1) D2(NC.D2) D3(NC.D3) D4(NC.D4) D12(NC.D12) D13(NC.D13) D14(NC.D14) E1(NC.E1) E2(NC.E2) E3(NC.E3) E5(NC.E5) E8(NC.E8) E9(NC.E9) E10(NC.E10) E12(NC.E12) E13(NC.E13) E14(NC.E14) F1(NC.F1) F2(NC.F2) F3(NC.F3) F10(NC.F10) F12(NC.F12) F13(NC.F13) F14(NC.F14) G1(NC.G1) G2(NC.G2) G3(NC.G3) G10(NC.G10) G12(NC.G12) G13(NC.G13) G14(NC.G14) H1(NC.H1) H2(NC.H2) H3(NC.H3) H5(NC.H5) H12(NC.H12) H13(NC.H13) H14(NC.H14) J1(NC.J1) J2(NC.J2) J3(NC.J3) J5(NC.J5) J12(NC.J12) J13(NC.J13) J14(NC.J14) K1(NC.K1) K2(NC.K2) K3(NC.K3) K6(NC.K6) K7(NC.K7) K10(NC.K10) K12(NC.K12) K13(NC.K13) K14(NC.K14) L1(NC.L1) L2(NC.L2) L3(NC.L3) L12(NC.L12) L13(NC.L13) L14(NC.L14) M1(NC.M1) M2(NC.M2) M3(NC.M3) M7(NC.M7) M8(NC.M8) M9(NC.M9) M10(NC.M10) M11(NC.M11) M12(NC.M12) M13(NC.M13) M14(NC.M14) MA4(NC.MA4) MA6(NC.MA6) MA9(NC.MA9) MA11(NC.MA11) MAE1(NC.MAE1) MAE14(NC.MAE14) MAG2(NC.MAG2) MAG13(NC.MAG13) MAH4(NC.MAH4) MAH6(NC.MAH6) MAH9(NC.MAH9) MAH11(NC.MAH11) MB2(NC.MB2) MB13(NC.MB13) MD1(NC.MD1) MD14(NC.MD14) N1(NC.N1) N3(NC.N3) N5(NC.N5) N6(NC.N6) N8(NC.N8) N9(NC.N9) N10(NC.N10) N11(NC.N11) N12(NC.N12) N13(NC.N13) N14(NC.N14) P1(NC.P1) P2(NC.P2) P7(NC.P7) P8(NC.P8) P9(NC.P9) P10(NC.P10) P11(NC.P11) P12(NC.P12) P13(NC.P13) P14(NC.P14)

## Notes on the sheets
sheet 13
- TI CONFIDENTIAL - NDA RESTRICTIONS
- Auto Cap Sizes Updated
- Work - In - Progress
- ON_OFF = 1 COMMANDS ALL NON-RTC DOMAINS TO BE ACTIVE
  ON_OFF = 0 COMMANDS ALL NON-RTC DOMAINS TO BE IN-ACTIVE
- Note: WAKEUP[3:0], including the
  GP1[x] functions, are
  input-only.
- ON RTC POWER DOMAIN
- ON RTC POWER DOMAIN
- CAPACITANCE      Commerical     Automotive
  Vaule            Size/X5R       Size/X7R
  .1uF             0201           0402
  .22uF            0201           0603
  .47uF            0201           0603
  1uF              0201           0603
  2.2uF            0402           0603
  4.7uF            0402           0805
  10uF             0402           0805
  22uF             0603           1206
- Preliminary Information - Subject to change
sheet 14
- TI CONFIDENTIAL - NDA RESTRICTIONS
- Auto Cap Sizes Updated
- Work - In - Progress
- CAPACITANCE      Commerical     Automotive
  Vaule            Size/X5R       Size/X7R
  .1uF             0201           0402
  .22uF            0201           0603
  .47uF            0201           0603
  1uF              0201           0603
  2.2uF            0402           0603
  4.7uF            0402           0805
  10uF             0402           0805
  22uF             0603           1206
- Preliminary Information - Subject to change
sheet 15
- TI CONFIDENTIAL - NDA RESTRICTIONS
- Auto Cap Sizes Updated
- Work - In - Progress
- CAPACITANCE      Commerical     Automotive
  Vaule            Size/X5R       Size/X7R
  .1uF             0201           0402
  .22uF            0201           0603
  .47uF            0201           0603
  1uF              0201           0603
  2.2uF            0402           0603
  4.7uF            0402           0805
  10uF             0402           0805
  22uF             0603           1206
- Preliminary Information - Subject to change
sheet 16
- TI CONFIDENTIAL - NDA RESTRICTIONS
- Auto Cap Sizes Updated
- Work - In - Progress
- CAPACITANCE      Commerical     Automotive
  Vaule            Size/X5R       Size/X7R
  .1uF             0201           0402
  .22uF            0201           0603
  .47uF            0201           0603
  1uF              0201           0603
  2.2uF            0402           0603
  4.7uF            0402           0805
  10uF             0402           0805
  22uF             0603           1206
- Preliminary Information - Subject to change
- Preliminary Information - Subject to change
sheet 17
- TI CONFIDENTIAL - NDA RESTRICTIONS
- Auto Cap Sizes Updated
- Work - In - Progress
- CAPACITANCE      Commerical     Automotive
  Vaule            Size/X5R       Size/X7R
  .1uF             0201           0402
  .22uF            0201           0603
  .47uF            0201           0603
  1uF              0201           0603
  2.2uF            0402           0603
  4.7uF            0402           0805
  10uF             0402           0805
  22uF             0603           1206
- Preliminary Information - Subject to change
sheet 18
- TI CONFIDENTIAL - NDA RESTRICTIONS
- Auto Cap Sizes Updated
  Verified EMI filters E3-E6 are +125C rated & 0805
- Work - In - Progress
- 1.8 VOLT
- CAPACITANCE      Commerical     Automotive
  Vaule            Size/X5R       Size/X7R
  .1uF             0201           0402
  .22uF            0201           0603
  .47uF            0201           0603
  1uF              0201           0603
  2.2uF            0402           0603
  4.7uF            0402           0805
  10uF             0402           0805
  22uF             0603           1206
- Preliminary Information - Subject to change
sheet 19
- TI CONFIDENTIAL - NDA RESTRICTIONS
- Auto Cap Sizes Updated
- Work - In - Progress
- 1.X VOLT
- 1.X VOLT
- 1.X VOLT
- CAPACITANCE      Commerical     Automotive
  Vaule            Size/X5R       Size/X7R
  .1uF             0201           0402
  .22uF            0201           0603
  .47uF            0201           0603
  1uF              0201           0603
  2.2uF            0402           0603
  4.7uF            0402           0805
  10uF             0402           0805
  22uF             0603           1206
- Preliminary Information - Subject to change
sheet 20
- TI CONFIDENTIAL - NDA
  RESTRICTIONS
- Work - In - Progress
- Preliminary Information - Subject to change
sheet 21
- TI CONFIDENTIAL - NDA RESTRICTIONS
- (C1,C2)
- (C3,C4)
- (C5,C6)
- Work - In - Progress
- 16GB - MTFC16GJVEC-4M PIN COMPATIBLE
   IN LARGER 169 WFBGA PACKAGE
- Preliminary Information - Subject to change
sheet 22
- TI CONFIDENTIAL - NDA RESTRICTIONS
- Work - In - Progress
- PCB Matched Group = H_QSPI_xxx
- Preliminary Information - Subject to change
sheet 23
- TI CONFIDENTIAL - NDA RESTRICTIONS
- Work - In - Progress
- Preliminary Information - Subject to change
sheet 24
- Auto Cap Sizes Updated
- TI CONFIDENTIAL - NDA RESTRICTIONS
- Work - In - Progress
- JP OR JT
- X16 MEMORY UPGRADED TO 256MX16
- CAPACITANCE      Commerical     Automotive
  Vaule            Size/X5R       Size/X7R
  .1uF             0201           0402
  .22uF            0201           0603
  .47uF            0201           0603
  1uF              0201           0603
  2.2uF            0402           0603
  4.7uF            0402           0805
  10uF             0402           0805
  22uF             0603           1206
- Preliminary Information - Subject to change
